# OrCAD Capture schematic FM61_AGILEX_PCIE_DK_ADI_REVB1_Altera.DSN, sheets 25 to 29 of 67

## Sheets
25 PCIe EP Edge Connector: size B
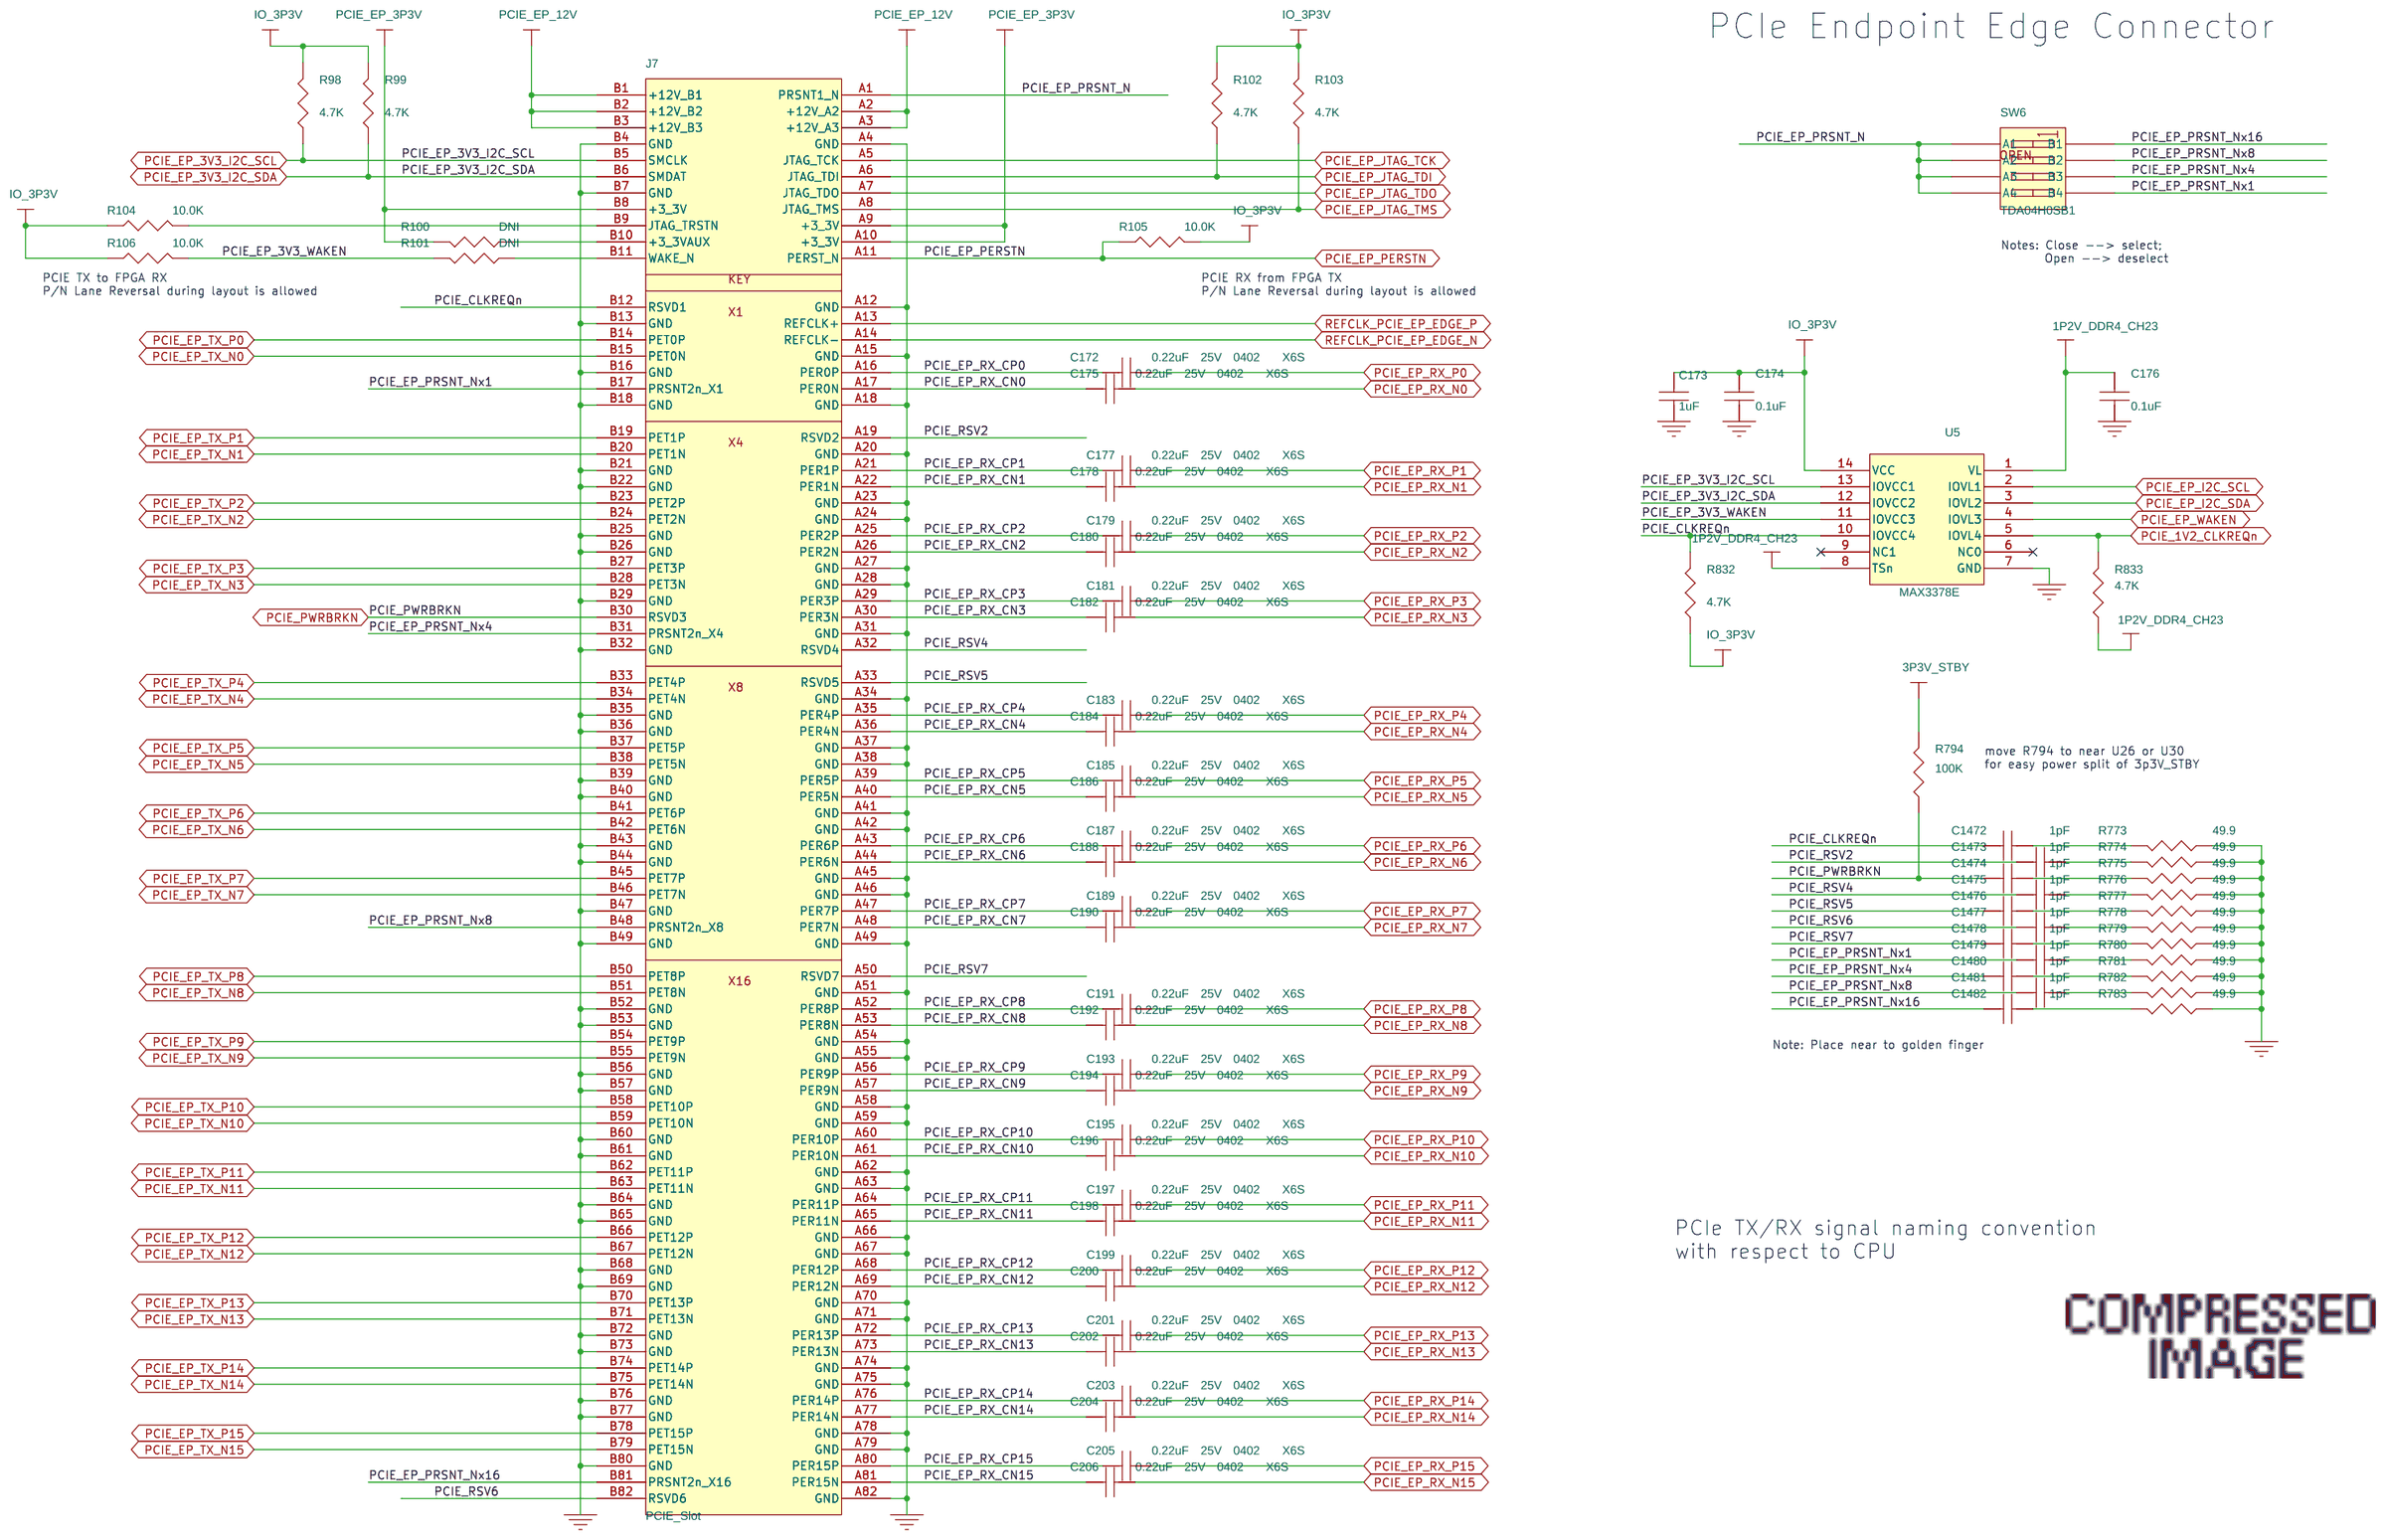
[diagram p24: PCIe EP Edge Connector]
26 FPGA BANK CONFIG SDM: size B
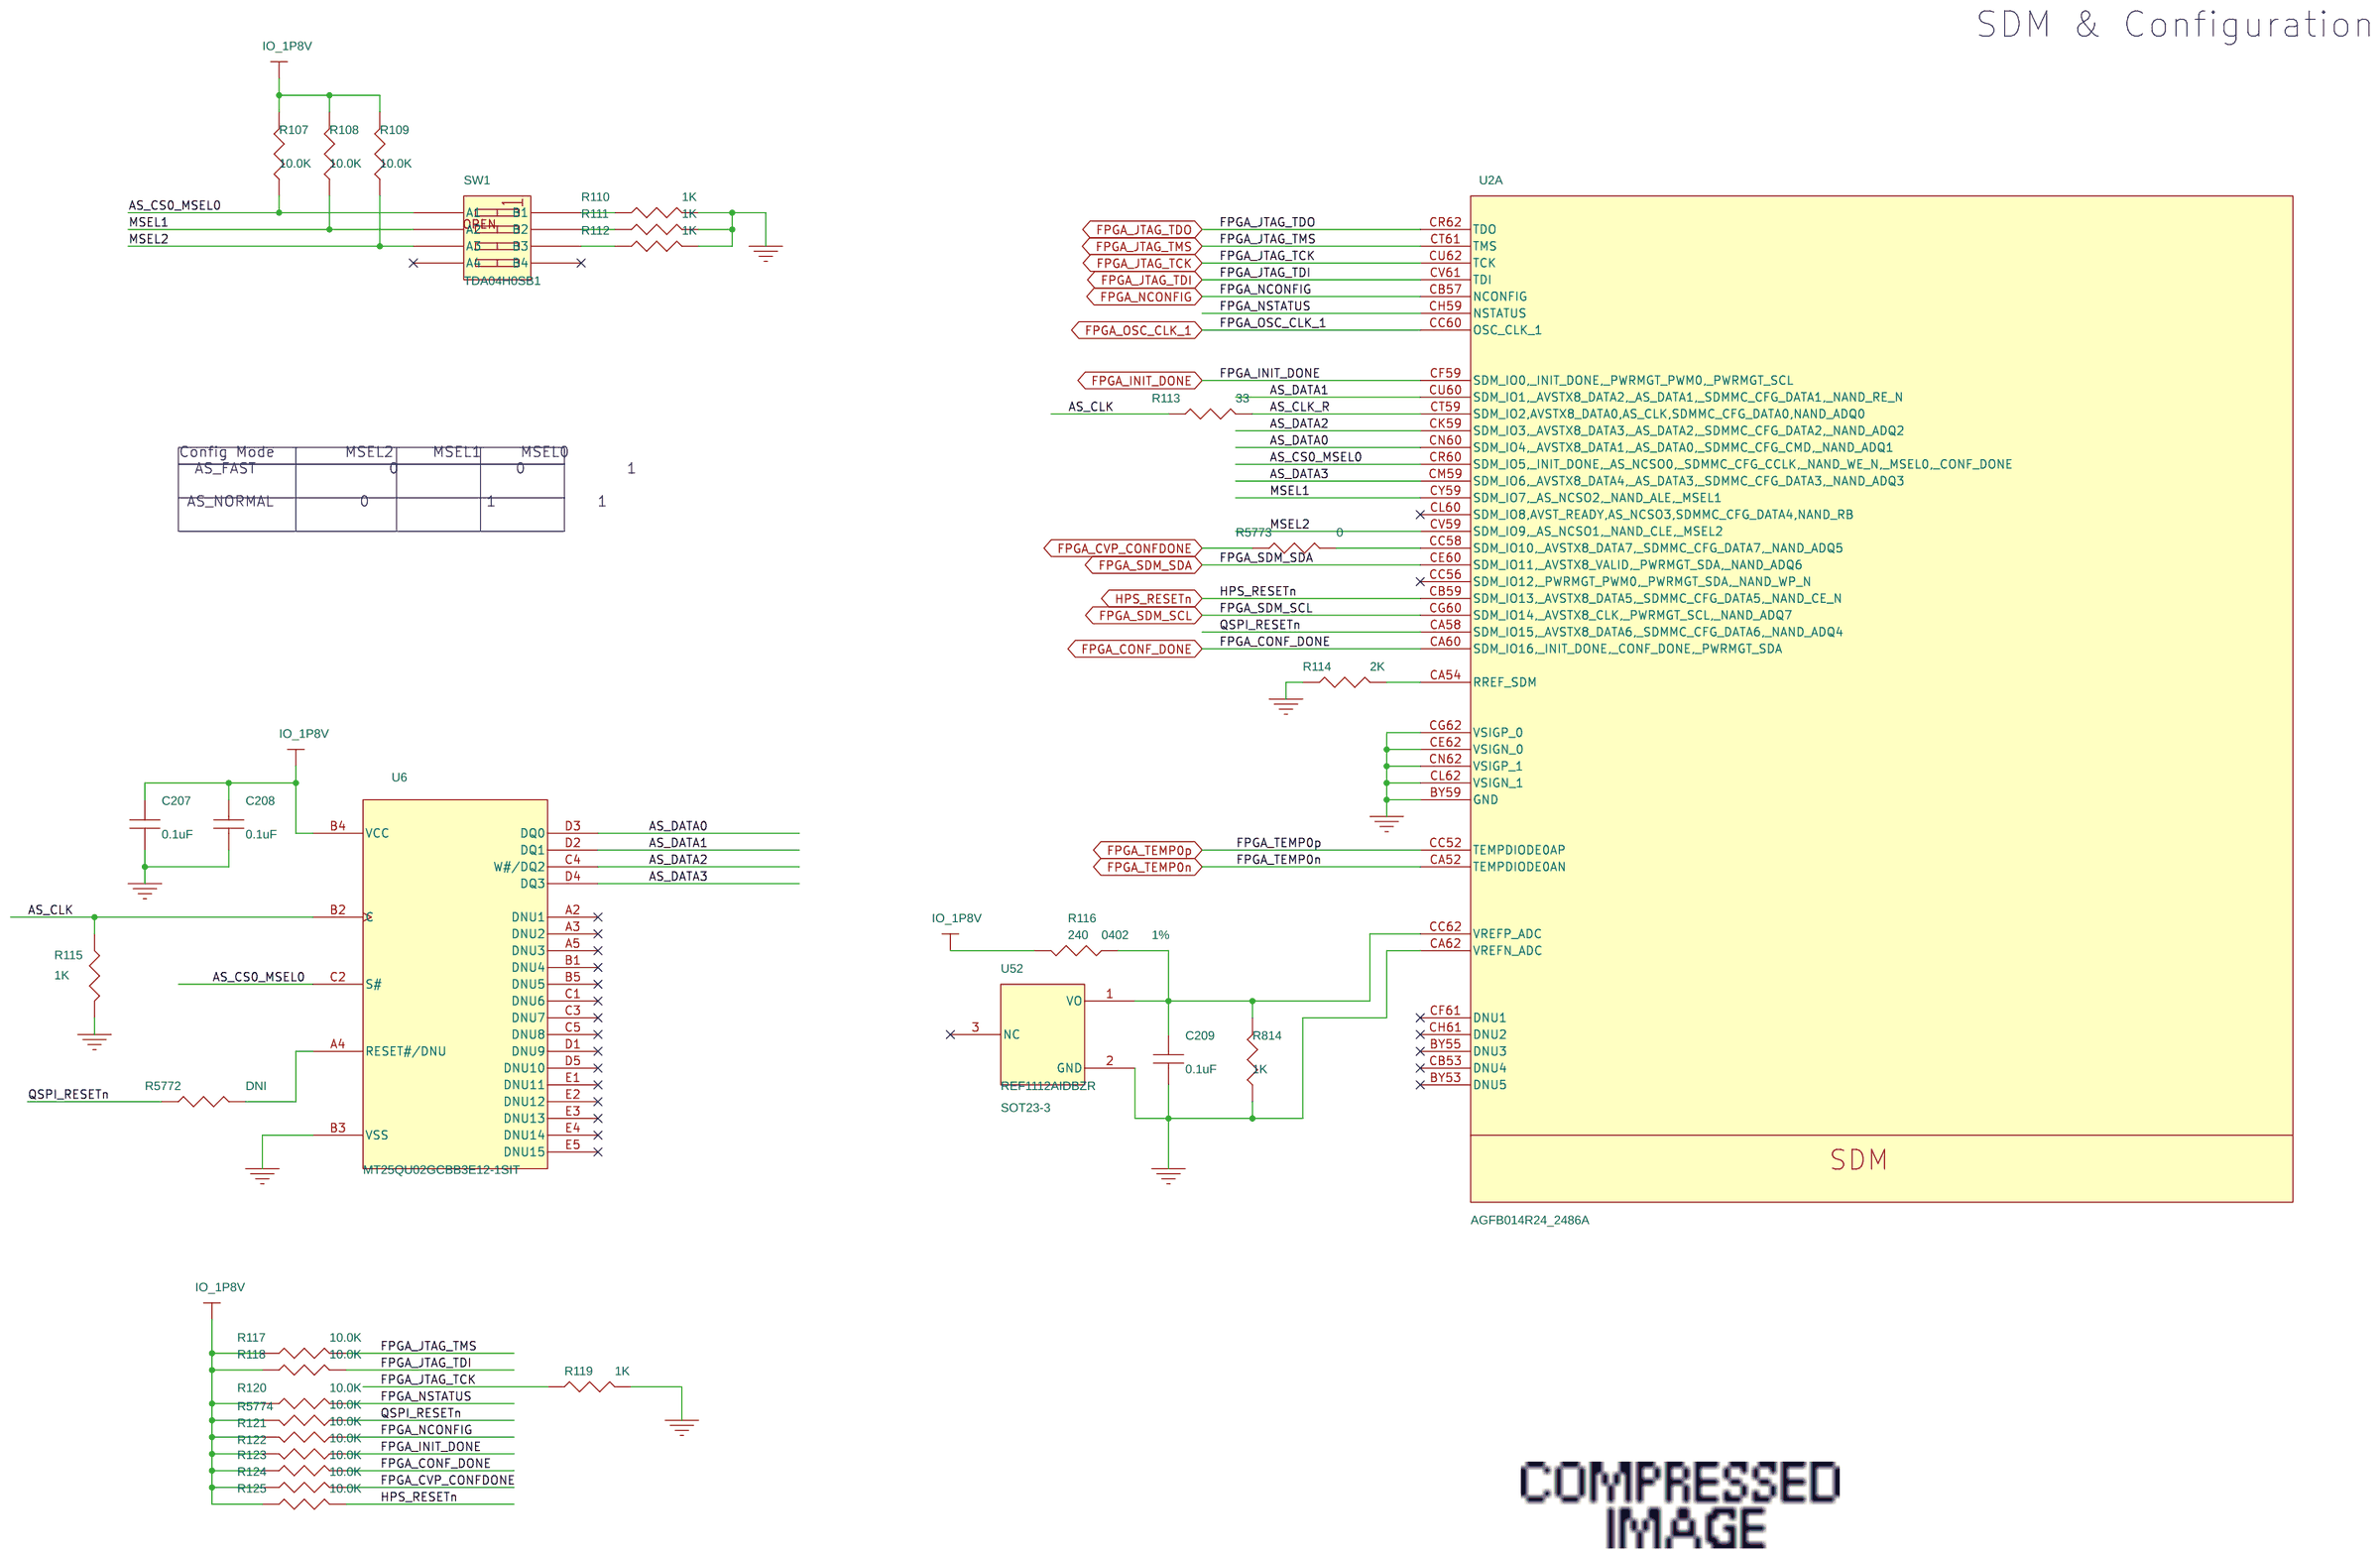
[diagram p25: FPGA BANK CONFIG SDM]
27 FPGA BANK HPS: size B
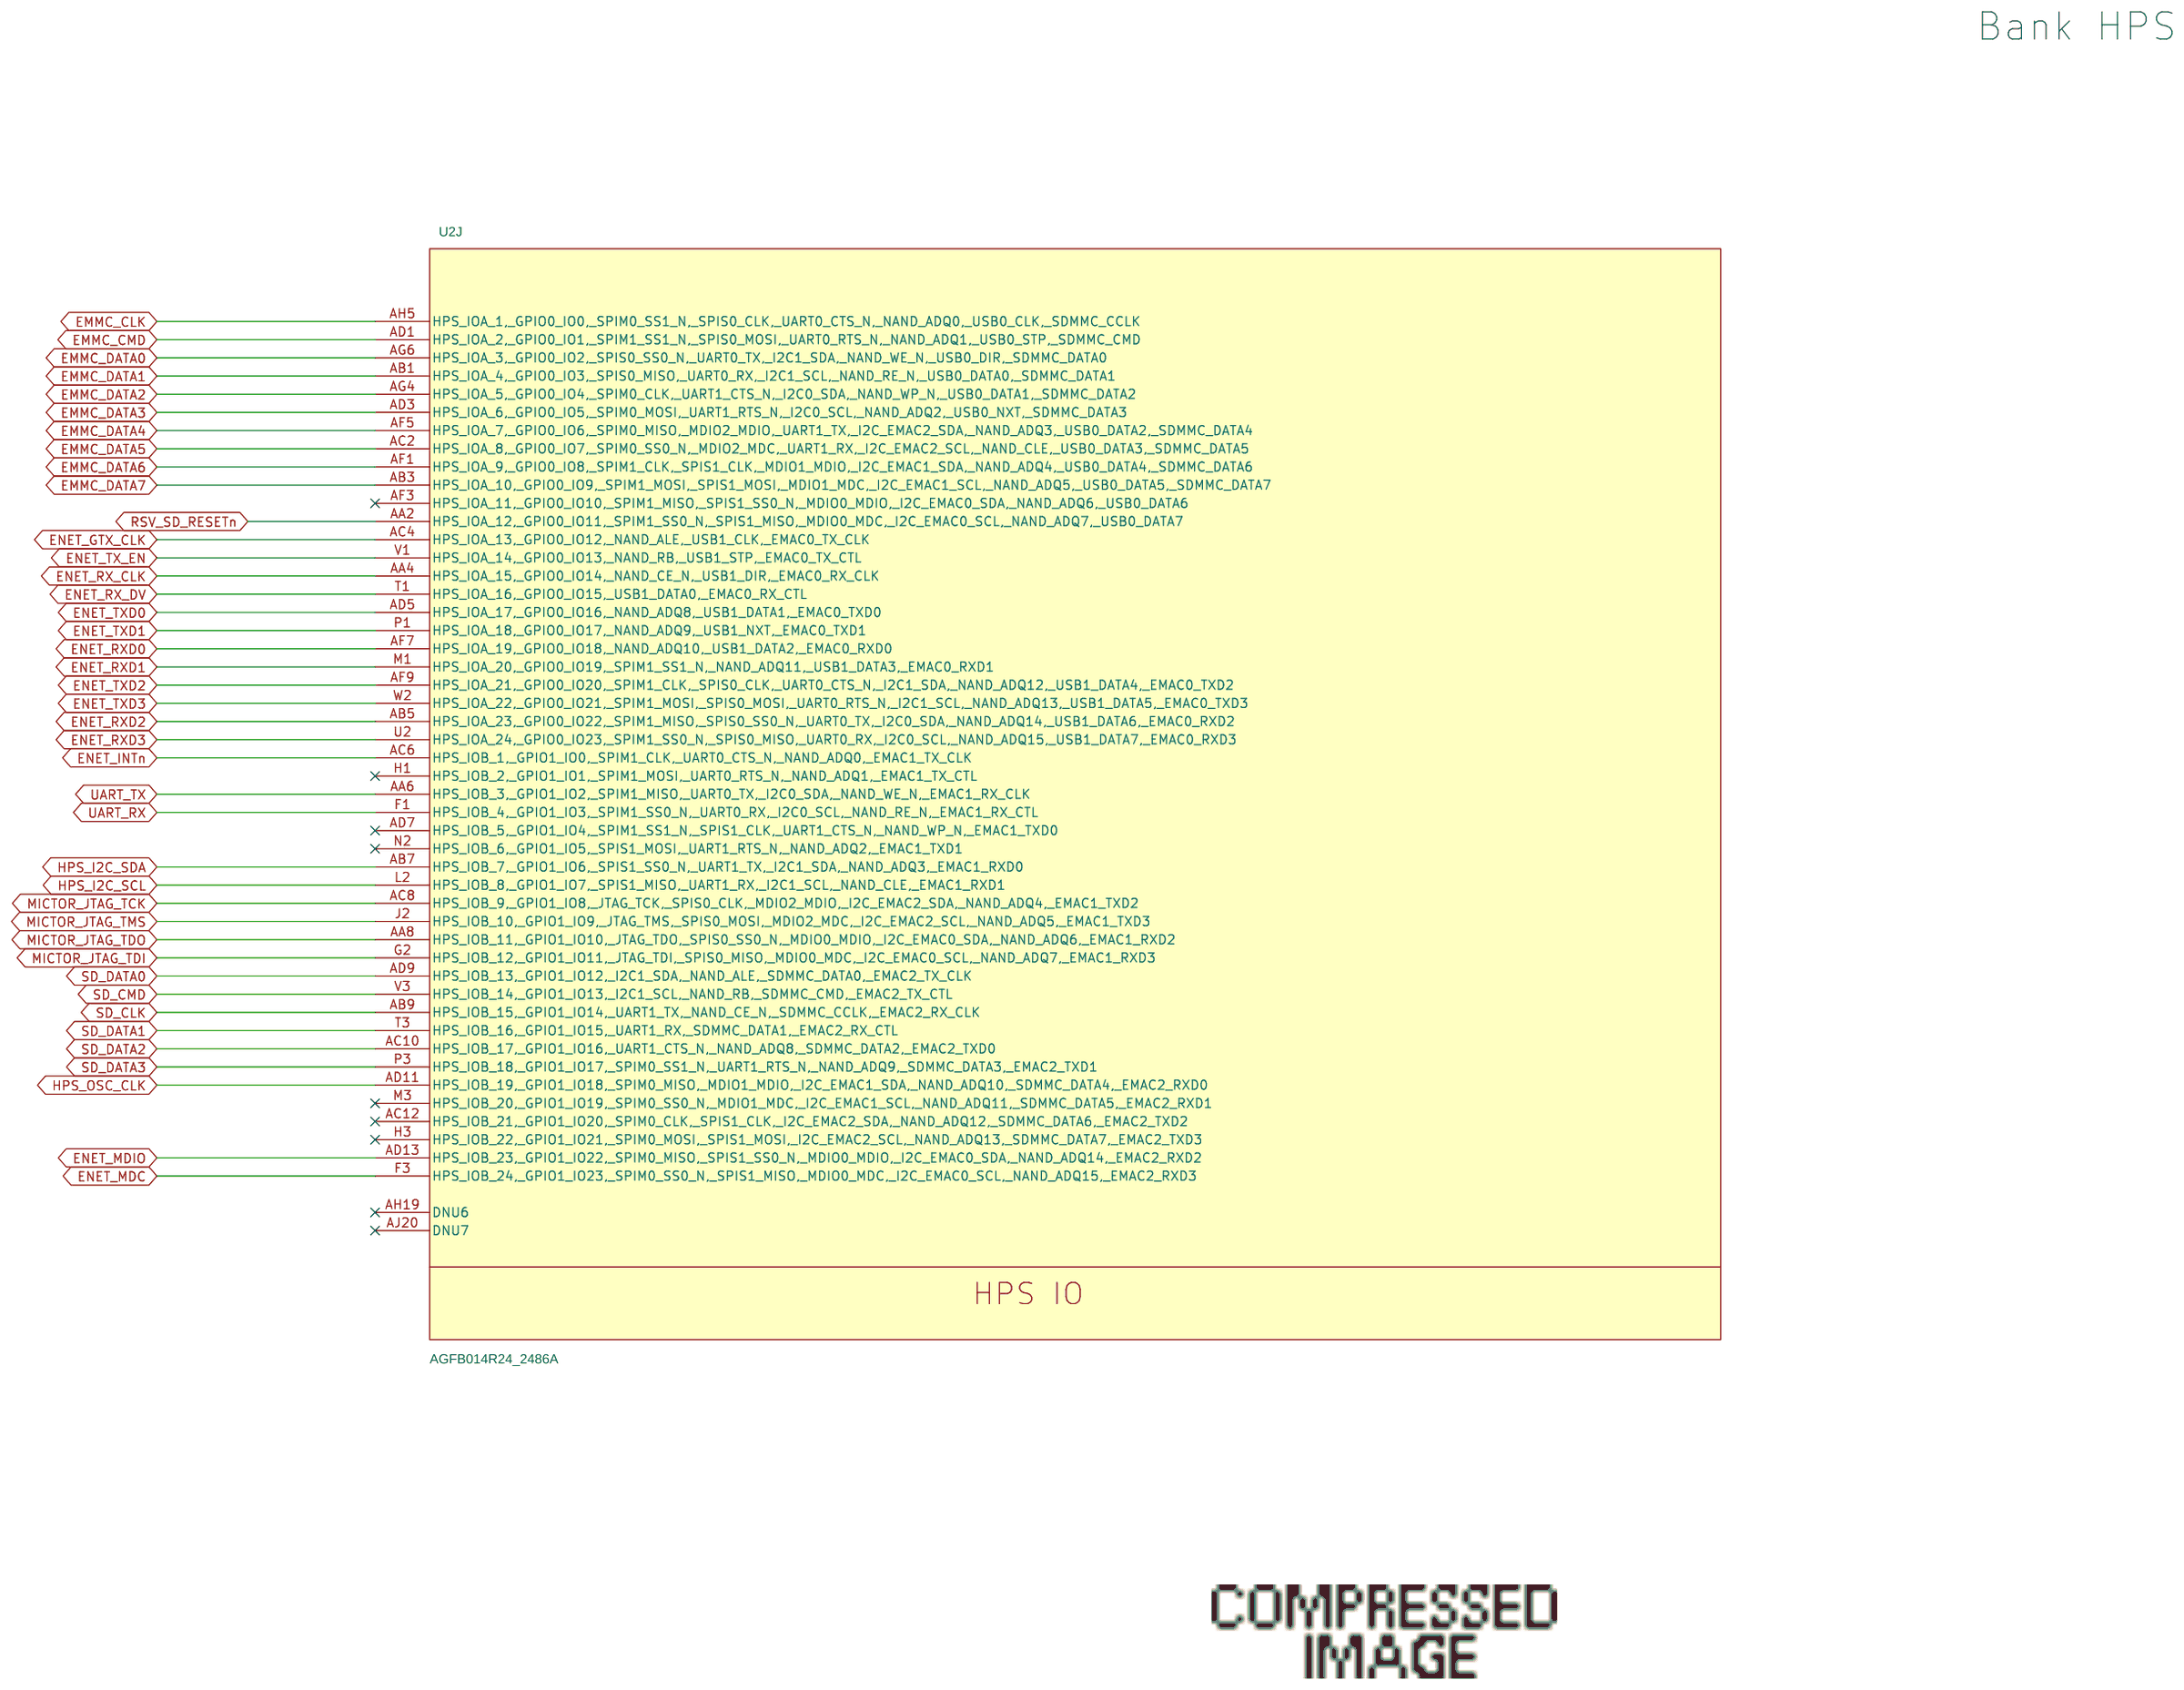
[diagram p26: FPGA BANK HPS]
28 Eth PHY: size B
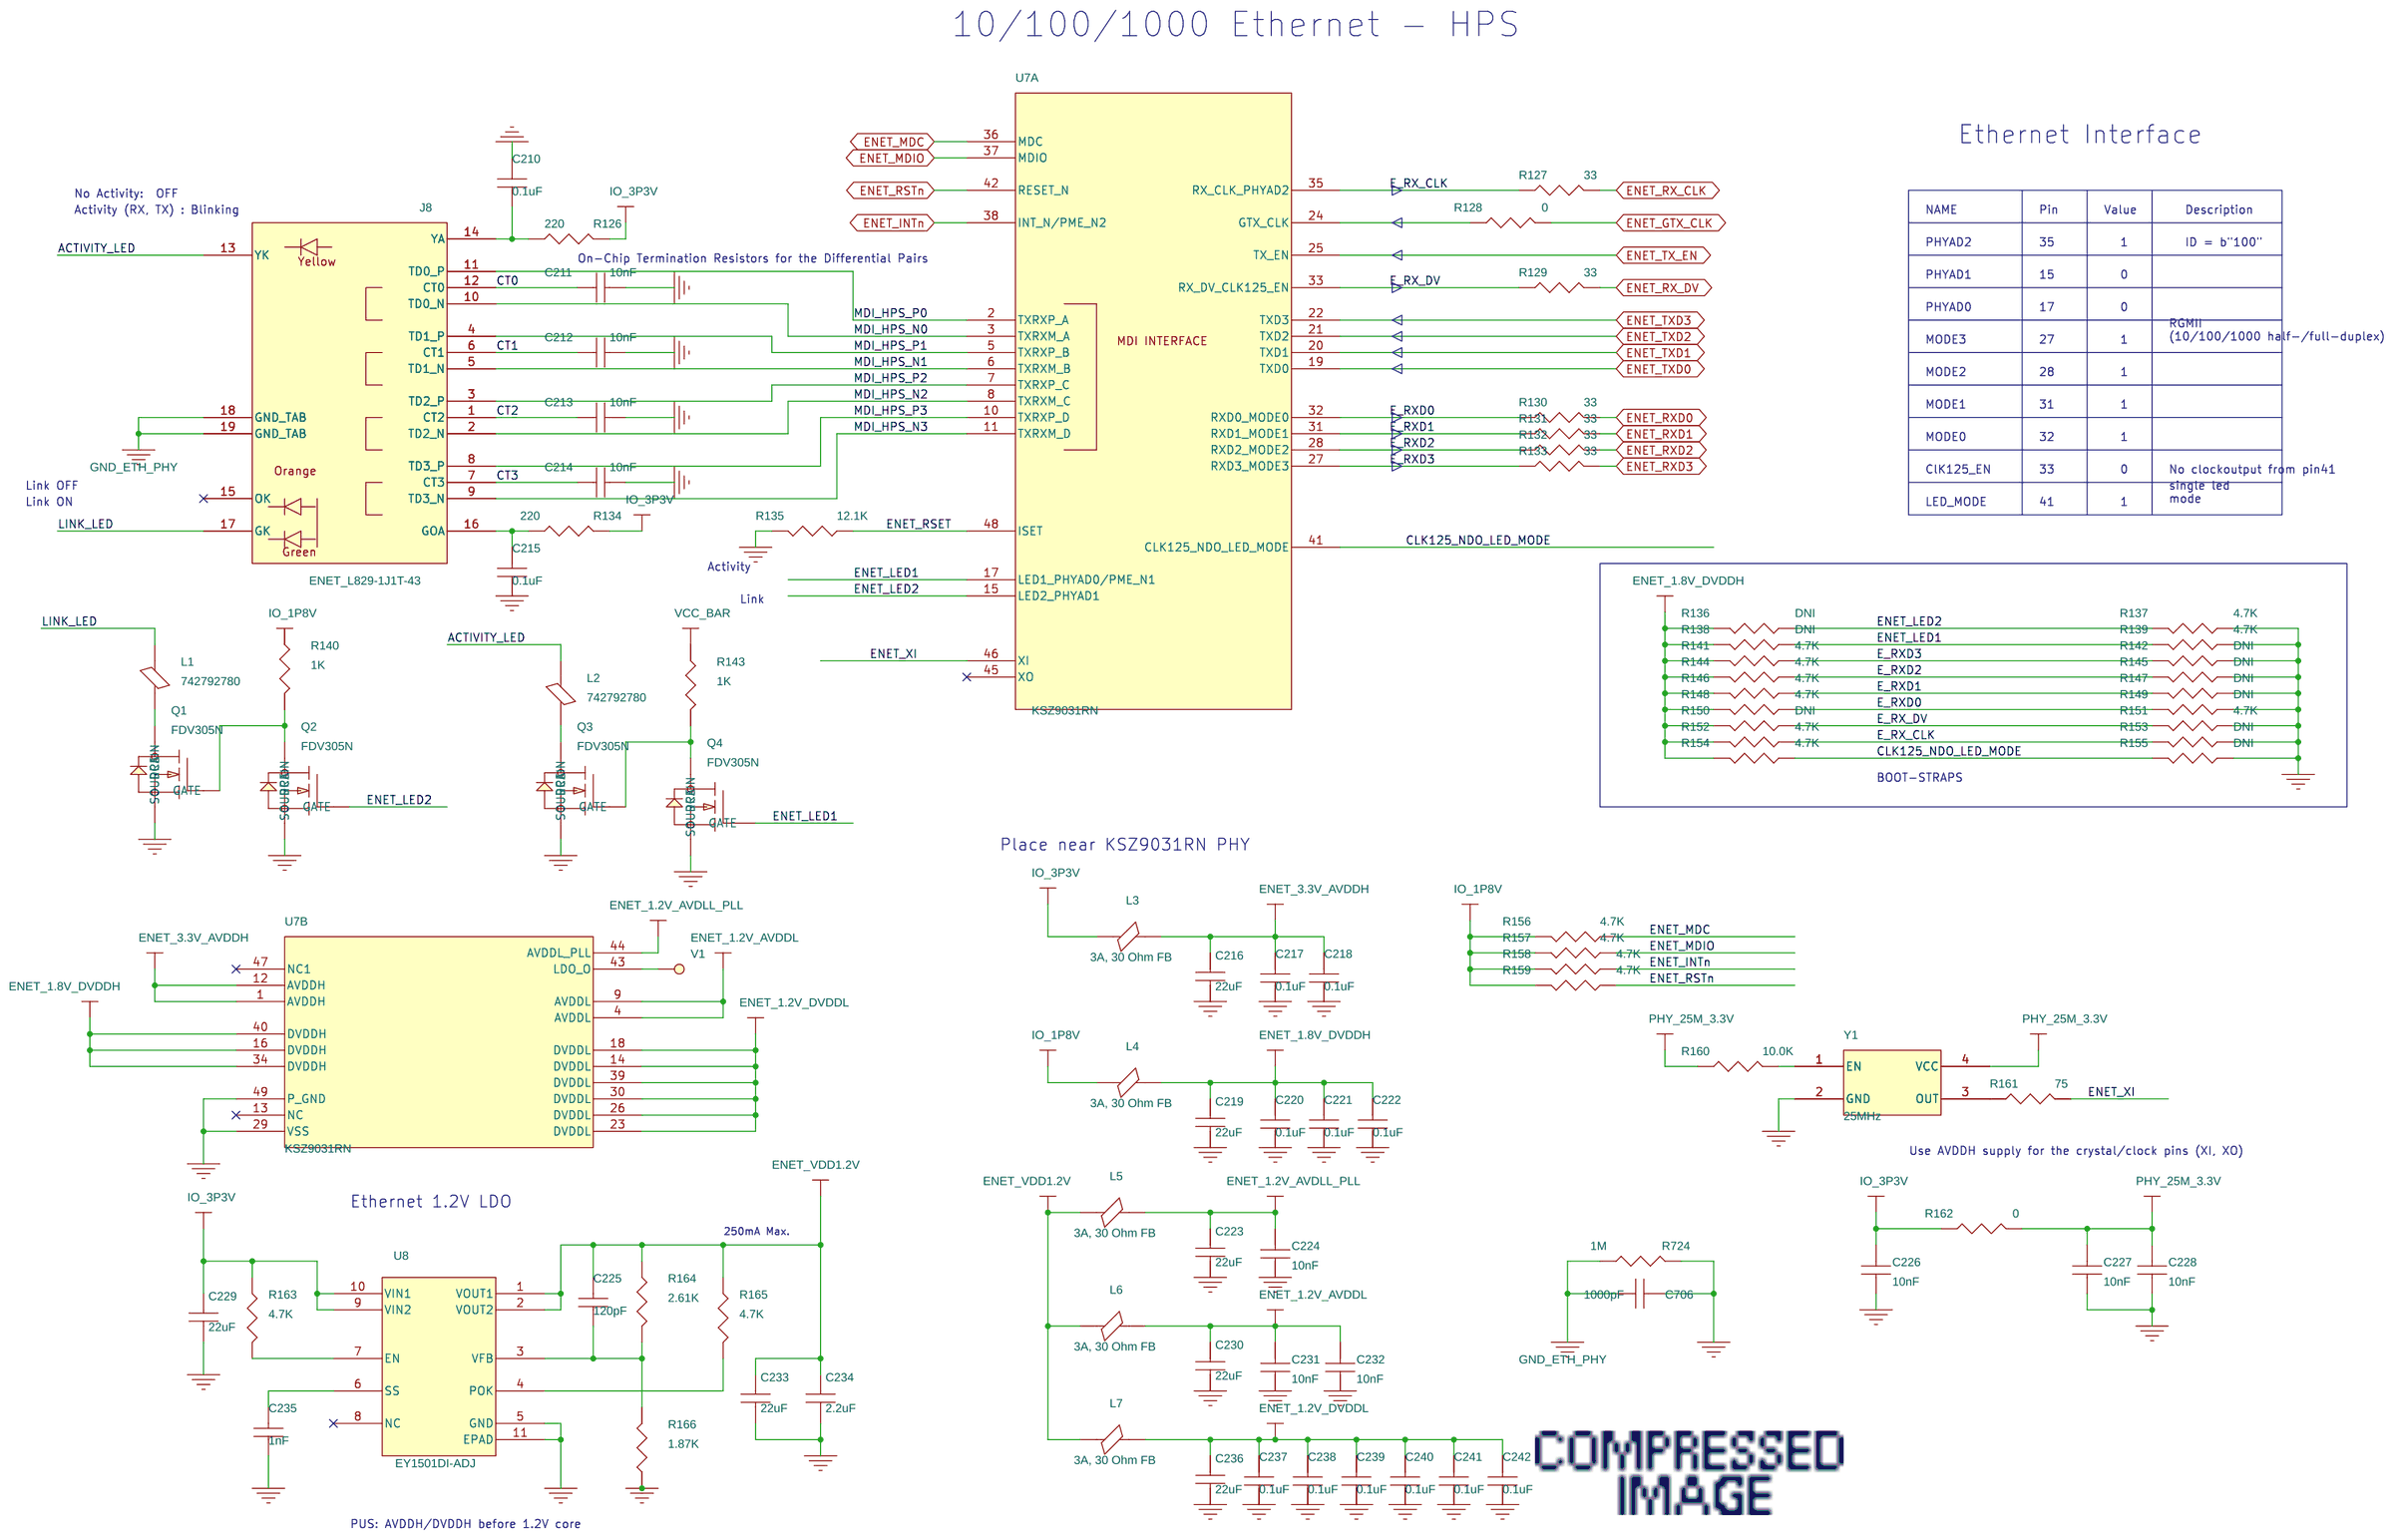
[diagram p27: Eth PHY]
29 UART: size B
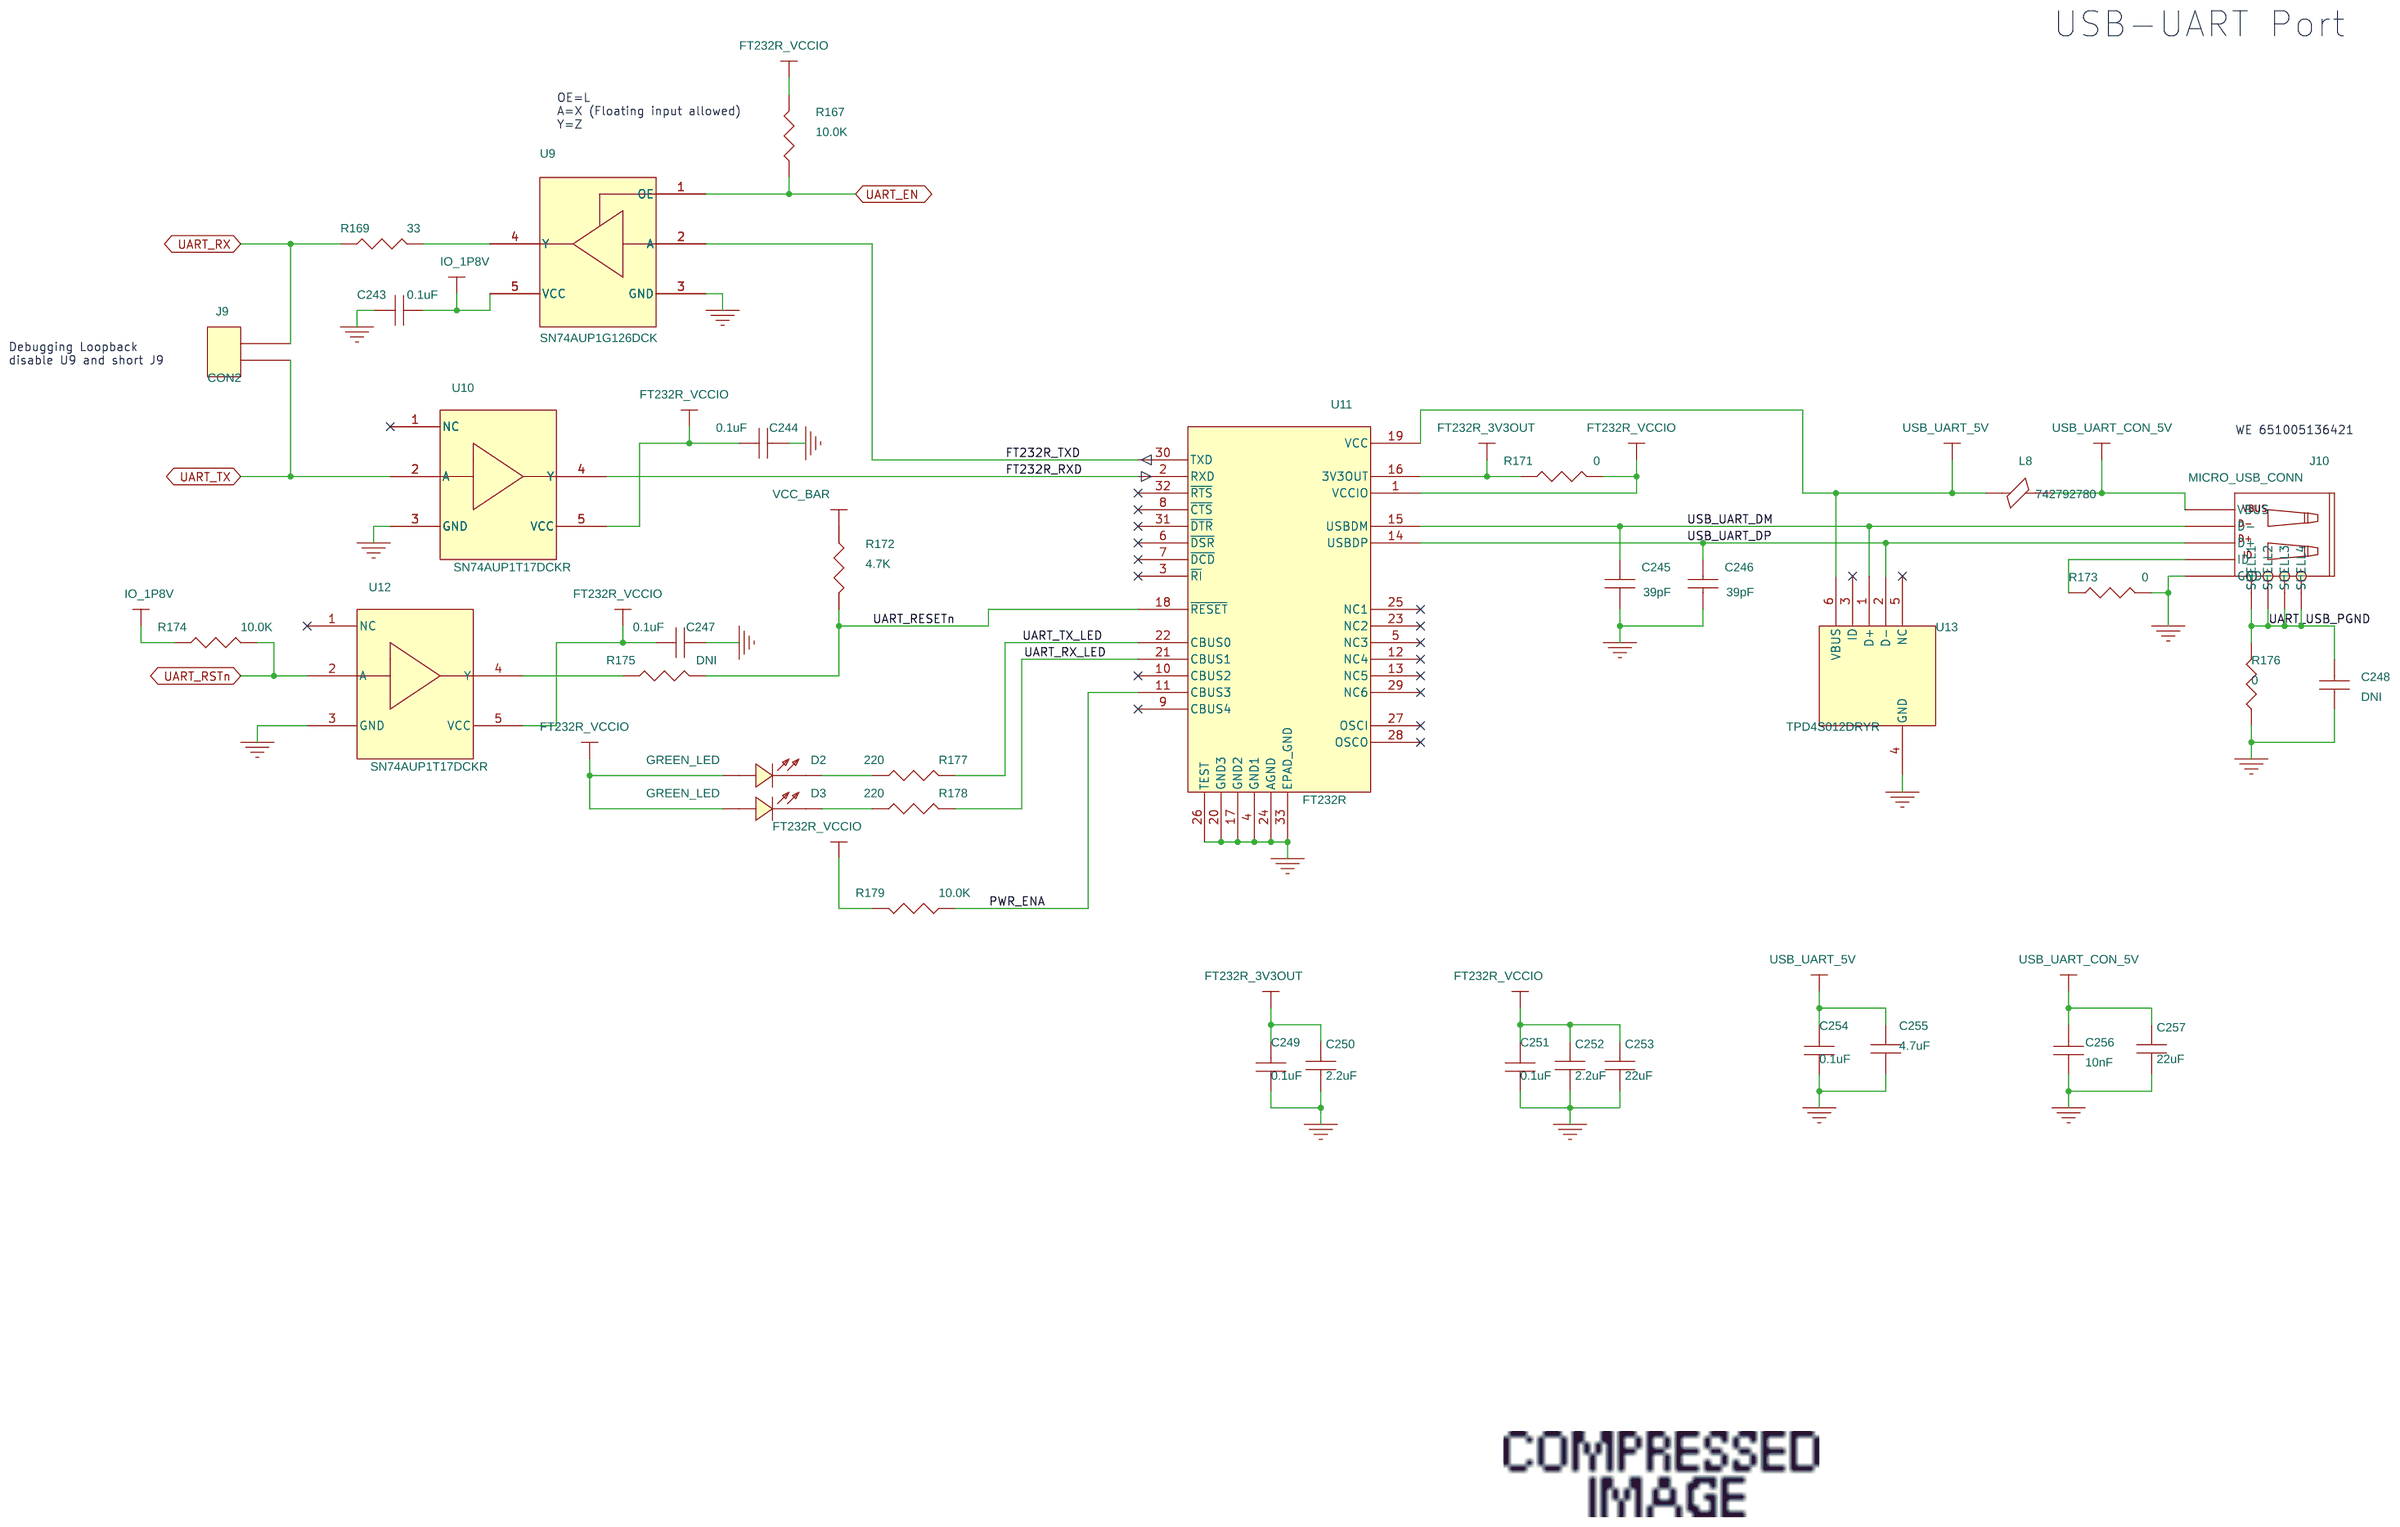
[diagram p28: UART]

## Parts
sheet Eth PHY
C210  0.1uF  [0402]
C211  10nF  [0402]
C212  10nF  [0402]
C213  10nF  [0402]
C214  10nF  [0402]
C215  0.1uF  [0402]
C216  22uF  [0603]
C217  0.1uF  [0402]
C218  0.1uF  [0402]
C219  22uF  [0603]
C220  0.1uF  [0402]
C221  0.1uF  [0402]
C222  0.1uF  [0402]
C223  22uF  [0603]
C224  10nF  [0402]
C225  120pF  [0402]
C226  10nF  [0402]
C227  10nF  [0402]
C228  10nF  [0402]
C229  22uF  [0603]
C230  22uF  [0603]
C231  10nF  [0402]
C232  10nF  [0402]
C233  22uF  [0603]
C234  2.2uF  [0603]
C235  1nF  [0402]
C236  22uF  [0603]
C237  0.1uF  [0402]
C238  0.1uF  [0402]
C239  0.1uF  [0402]
C240  0.1uF  [0402]
C241  0.1uF  [0402]
C242  0.1uF  [0402]
C706  1000pF  [1206]
J8  ENET_L829-1J1T-43  [bel_l829-1j1t-43]
L1  742792780  [0402]
L2  742792780  [0402]
L3  3A, 30 Ohm FB  [ind_0603]
L4  3A, 30 Ohm FB  [ind_0603]
L5  3A, 30 Ohm FB  [ind_0603]
L6  3A, 30 Ohm FB  [ind_0603]
L7  3A, 30 Ohm FB  [ind_0603]
Q1  FDV305N  [SOT23]
Q2  FDV305N  [SOT23]
Q3  FDV305N  [SOT23]
Q4  FDV305N  [SOT23]
R126  220  [0402]
R127  33  [0402]
R128  0  [0402]
R129  33  [0402]
R130  33  [0402]
R131  33  [0402]
R132  33  [0402]
R133  33  [0402]
R134  220  [0402]
R135  12.1K  [0402]
R136  DNI  [0402]
R137  4.7K  [0402]
R138  DNI  [0402]
R139  4.7K  [0402]
R140  1K  [0402]
R141  4.7K  [0402]
R142  DNI  [0402]
R143  1K  [0402]
R144  4.7K  [0402]
R145  DNI  [0402]
R146  4.7K  [0402]
R147  DNI  [0402]
R148  4.7K  [0402]
R149  DNI  [0402]
R150  DNI  [0402]
R151  4.7K  [0402]
R152  4.7K  [0402]
R153  DNI  [0402]
R154  4.7K  [0402]
R155  DNI  [0402]
R156  4.7K  [0402]
R157  4.7K  [0402]
R158  4.7K  [0402]
R159  4.7K  [0402]
R160  10.0K  [0402]
R161  75  [0402]
R162  0  [0402]
R163  4.7K  [0402]
R164  2.61K  [0402]
R165  4.7K  [0402]
R166  1.87K  [0402]
R724  1M  [0402]
U7  KSZ9031RN  [QFN48]  (sections A,B)
U8  EY1501DI-ADJ  [DFN-10]
V1  VIA_1  [STAR_VIA]
Y1  25MHz  [OSC7050]
sheet FPGA BANK CONFIG SDM
C207  0.1uF  [0402]
C208  0.1uF  [0402]
C209  0.1uF  [0402]
R107  10.0K  [0402]
R108  10.0K  [0402]
R109  10.0K  [0402]
R110  1K  [0402]
R111  1K  [0402]
R112  1K  [0402]
R113  33  [0402]
R114  2K  [0402]
R115  1K  [0402]
R116  240  [0402]
R117  10.0K  [0402]
R118  10.0K  [0402]
R119  1K  [0402]
R120  10.0K  [0402]
R121  10.0K  [0402]
R122  10.0K  [0402]
R123  10.0K  [0402]
R124  10.0K  [0402]
R125  10.0K  [0402]
R814  1K  [0402]
R5772  DNI  [0402]
R5773  0  [0402]
R5774  10.0K  [0402]
SW1  TDA04H0SB1  [DIPSWITCH_SMT_QUAD]
U6  MT25QU02GCBB3E12-1SIT  [T-PBGA24]
U52  REF1112AIDBZR  [SOT23-3]
sheet FPGA Gnd 2
U2  AGFB014R24_2486A  [FBGA2486A_HEX]  (sections A,B,C,D,E,F,G,H,I,J,K,L,M,N,O,P,Q,R,S,T,U,V,W,X)
sheet PCIe EP Edge Connector
C172  0.22uF  [0402]
C173  1uF  [0402]
C174  0.1uF  [0402]
C175  0.22uF  [0402]
C176  0.1uF  [0402]
C177  0.22uF  [0402]
C178  0.22uF  [0402]
C179  0.22uF  [0402]
C180  0.22uF  [0402]
C181  0.22uF  [0402]
C182  0.22uF  [0402]
C183  0.22uF  [0402]
C184  0.22uF  [0402]
C185  0.22uF  [0402]
C186  0.22uF  [0402]
C187  0.22uF  [0402]
C188  0.22uF  [0402]
C189  0.22uF  [0402]
C190  0.22uF  [0402]
C191  0.22uF  [0402]
C192  0.22uF  [0402]
C193  0.22uF  [0402]
C194  0.22uF  [0402]
C195  0.22uF  [0402]
C196  0.22uF  [0402]
C197  0.22uF  [0402]
C198  0.22uF  [0402]
C199  0.22uF  [0402]
C200  0.22uF  [0402]
C201  0.22uF  [0402]
C202  0.22uF  [0402]
C203  0.22uF  [0402]
C204  0.22uF  [0402]
C205  0.22uF  [0402]
C206  0.22uF  [0402]
C1472  1pF  [0402]
C1473  1pF  [0402]
C1474  1pF  [0402]
C1475  1pF  [0402]
C1476  1pF  [0402]
C1477  1pF  [0402]
C1478  1pF  [0402]
C1479  1pF  [0402]
C1480  1pF  [0402]
C1481  1pF  [0402]
C1482  1pF  [0402]
J7  PCIE_Slot  [PCIX-16PORT]
R98  4.7K  [0402]
R99  4.7K  [0402]
R100  DNI  [0402]
R101  DNI  [0402]
R102  4.7K  [0402]
R103  4.7K  [0402]
R104  10.0K  [0402]
R105  10.0K  [0402]
R106  10.0K  [0402]
R773  49.9  [0402]
R774  49.9  [0402]
R775  49.9  [0402]
R776  49.9  [0402]
R777  49.9  [0402]
R778  49.9  [0402]
R779  49.9  [0402]
R780  49.9  [0402]
R781  49.9  [0402]
R782  49.9  [0402]
R783  49.9  [0402]
R794  100K  [0402]
R832  4.7K  [0402]
R833  4.7K  [0402]
SW6  TDA04H0SB1  [DIPSWITCH_SMT_QUAD]
U5  MAX3378E  [TSSOP-14]
sheet UART
C243  0.1uF  [0402]
C244  0.1uF  [0402]
C245  39pF  [0402]
C246  39pF  [0402]
C247  0.1uF  [0402]
C248  DNI  [0402]
C249  0.1uF  [0402]
C250  2.2uF  [0603]
C251  0.1uF  [0402]
C252  2.2uF  [0603]
C253  22uF  [0603]
C254  0.1uF  [0402]
C255  4.7uF  [0805]
C256  10nF  [0402]
C257  22uF  [0603]
D2  GREEN_LED  [LED_0603]
D3  GREEN_LED  [LED_0603]
J9  CON2  [HDR2x1_100MIL]
J10  MICRO_USB_CONN  [molex-micro-usb-47589-001]
L8  742792780  [0402]
R167  10.0K  [0402]
R169  33  [0402]
R171  0  [0402]
R172  4.7K  [0402]
R173  0  [0402]
R174  10.0K  [0402]
R175  DNI  [0402]
R176  0  [0402]
R177  220  [0402]
R178  220  [0402]
R179  10.0K  [0402]
U9  SN74AUP1G126DCK  [SC70_TI]
U10  SN74AUP1T17DCKR  [SC70_TI]
U11  FT232R  [Qfn32-ftdi]
U12  SN74AUP1T17DCKR  [SC70_TI]
U13  TPD4S012DRYR  [SON6]

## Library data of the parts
C210 C215 C217 C218 C220-C222 C237-C242 = CAP: CAP CER 0.1UF 25V 20% X7R 0402; IPN: K13660-001; Item Num: P03-17618R; LIFECYCLE_PHASE: Active; Manufacturer: TDK Electronics; Manufacturer Part Num: C1005X7R1E104M; Price: 0; RoHS Compliant: RoHS Compliant
C211-C214 C224 C226-C228 C231 C232 C256 = CAP: CAP - CER, 10NF, 50V, +/-10%, X7R, 0402 SMD; IPN: A36096-100; Item Num: P03-16318R; Manufacturer: Murata; Manufacturer Part Num: GRM155R71H103KA88D; Price: 0; RoHS Compliant: RoHS Compliant
C216 C219 C223 C229 C230 C233 C236 C253 C257 = CAP: CAP 22UF CER 20% 6.3VDC X5R 0603 SMT; IPN: H48508-001; Item Num: P03-17794R; Manufacturer: Murata; Manufacturer Part Num: GRM188R60J226MEA0; Part Number: P03-17794R; Tolerance: +/-20%; Voltage: 6.3V
C225 = CAP: CAP - CER, 120PF, 50V, 5%, C0G, 0402; IPN: K13771-001; Item Num: P03-15872R; LIFECYCLE_PHASE: Active; Manufacturer: Murata; Manufacturer Part Num: GRM1555C1H121JA01D; Price: 0; RoHS Compliant: RoHS Compliant
C234 = CAP: CAP, CERAMIC, 2.2UF, 10%, 10VDC, X5R, 0603; IPN: K13568-001; Item Num: P03-15213R; LIFECYCLE_PHASE: Active; Manufacturer: Murata; Manufacturer Part Num: GRM188R61A225KE34x; RoHS Compliant: RoHS Compliant
C235 = CAP: CAP - CER, 1NF, 10%, 50V, X7R, 0402; IPN: G40798-001; Item Num: P03-15174R; LIFECYCLE_PHASE: Active; Manufacturer: Murata; Manufacturer Part Num: GRM155R71H102KA01D; Price: 0; RoHS Compliant: RoHS Compliant
C706 = CAP: CAP CER 1000PF 1000V X7R 1206; AGILE_LINK: http://sj-agile9app/Agile/PLMServlet?action=OpenEmailObject&classid=10000&objid=215384813; IPN: K13749-001; Item Num: P03-17910R; LIFECYCLE_PHASE: Active; Lead Free Status: Lead Free; MFR_LIFECYCLE: Active; Manufacturer: Murata; Manufacturer Part Num: GRM31BR73A102KW01L; Num Pins: 2; PACKAGING: Tape & Reel (TR); PART_SUBCLASS: CAPACITORS; RATED_VOLTAGE: 1000V; RoHS Compliant: RoHS Compliant; Supplier Part Num: GRM31BR73A102KW01L; Tolerance: +/-10%
J8 = ENET_L829-1J1T-43_2: CONN - RJ45 SINGLE PORT, 1000BASE-T GIGABIT ETHERNET MAGJACK 1 X 1 WITHLEDS, LOW PROFILE; IPN: C98527-001; Item Num: P23-38514R; Manufacturer: Bel Stewart Connector; Manufacturer Part Num: L829-1J1T-43; RoHS Compliant: RoHS Compliant
L1 L2 L8 = BEAD_FERRITE_SM: IND - SMD EMI FILTERS/CHIP FERRITE BEAD, 220-OHM @ 100MHZ, 0.35-OHM DCR, 0402; IPN: G79186-002; Item Num: P04-17068R; Manufacturer: Wurth Elektronik; Num Pins: 2; RoHS Compliant: RoHS Compliant
L3-L7 = IND_Ferrite_0603_3A_30_Ohms: IPN: K14405-001
Q1-Q4 = NMOS_3Pin: IC, MOSFET, N-CHANNEL, 20V; DCR: 0.3; IPN: K21465-001; Item Num: P18-31002R; Manufacturer: Fairchild Semiconductor; Voltage: 20V
R126 R134 = RESISTOR: RES, 220 OHMS, 5%, 1/16W, 0402; IPN: K15619-001; Item Num: P02-14107R; Manufacturer: Panasonic; Manufacturer Part Num: ERJ-2GEJ221X; Price: 0; RoHS Compliant: RoHS Compliant
R127 R129-R133 R169 = RESISTOR: RES 33 OHM 1/16W 5% 0402 SMD; IPN: K15753-001; Item Num: P02-14029R; LIFECYCLE_PHASE: Active; Manufacturer: Panasonic; Manufacturer Part Num: ERJ-2GEJ330X; RoHS Compliant: RoHS Compliant
R128 R162 R171 R173 = RESISTOR: RES ZERO OHM 1/16W 5% 0402 SMD; IPN: H30887-001; Item Num: P02-14020R; Manufacturer: Panasonic; Manufacturer Part Num: ERJ-2GE0R00X; Num Pins: 2; RoHS Compliant: RoHS Compliant
R135 = RESISTOR: RES-SMD 1/16watt 12.1Kohms 1% 0402; IPN: A93548-018; Item Num: P02-17669R; Manufacturer: Vishay; Manufacturer Part Num: CRCW040212K1FKED; Price: 0
R136 R138 R141 R142 R144-R151 R153 R154 R156-R159 R163 R165 = RESISTOR: RES,4.70K OHMS,1.0%,1/16W,0402; IPN: D60468-001; Item Num: P02-11384R; LIFECYCLE_PHASE: Active; Manufacturer: Vishay; Manufacturer Part Num: CRCW04024K70FKED; RoHS Compliant: RoHS Compliant
R137 R139 R152 R155 = RESISTOR: RES,4.70K OHMS,1.0%,1/16W,0402; IPN: D60468-001; Item Num: P02-11384R; LIFECYCLE_PHASE: Active; Manufacturer: Vishay; Manufacturer Part Num: CRCW04024K70FKED
R140 R143 = RESISTOR: RES,1.00K OHMS,1.0%,1/16W,0402; IPN: G60609-021; Item Num: P02-11372R; Manufacturer: Panasonic; Manufacturer Part Num: ERJ-2RKF1001X; Num Pins: 2; RoHS Compliant: RoHS Compliant
R160 R174 = RESISTOR: RES,10.0K OHMS,1.0%,1/16W, 0402; IPN: A93548-034; Item Num: P02-11364R; Manufacturer: Panasonic; Manufacturer Part Num: ERJ-2RKF1002X; Price: 0; RoHS Compliant: RoHS Compliant
R161 = RESISTOR: RES, 75 OHM, 5%, 1/16W, 0402; IPN: K15616-001; Item Num: P02-14103R; LIFECYCLE_PHASE: Active; Manufacturer: Panasonic; Manufacturer Part Num: ERJ-2RKF75ROX; Manufacturer Part Number: PANASONIC; RoHS Compliant: RoHS Compliant
R164 = R: RES - 2.61K OHM, 1%,1/10W, 0402 SMD; IPN: G41697-001; Item Num: P02-16710R; Manufacturer: Panasonic; Manufacturer Part Num: ERJ-2RKF2611x; Price: 0; RoHS Compliant: RoHS Compliant
R166 = RESISTOR: RES - 1.87K OHMS, 1.0%, 1/16W, 0402; IPN: K16301-001; Item Num: P02-16414R; Manufacturer: Vishay; Manufacturer Part Num: CRCW04021K87FKxx; RoHS Compliant: RoHS Compliant
R724 = RESISTOR: RES,1M OHMS,5.0%,1/16W,0402; AGILE_LINK: http://sj-agile9app/Agile/PLMServlet?action=OpenEmailObject&classid=10000&objid=146548997; IPN: K15866-001; Item Num: P02-11390R; LIFECYCLE_PHASE: Active; Lead Free Status: No; MFR_LIFECYCLE: Active; Manufacturer: Panasonic; Manufacturer Part Num: ERJ-2GEJ105X; Num Pins: 2; PART_SUBCLASS: RESISTORS; POWER: 1/16W; RoHS Compliant: Yes; TOLERANCE: +/-5%
U7 = KSZ9031RN_4: IC- PHY 1-CH 10MBPS/100MBPS/1GBPS 48-PIN QFN; IPN: J49350-001; Item Num: P01-17926R; Manufacturer: Micrel Semiconductor; Manufacturer Part Num: KSZ9031RNXCA; RoHS Compliant: RoHS Compliant
U8 = EY1501DI-ADJ: IC,LIN,DFN,ISL80101-AD,VREF; IPN: H38446-001; Item Num: P01-18061R; Manufacturer: Altera Corporation; Manufacturer Part Num: ISL80101IRAJZ-T
V1 = VIA_1
Y1 = OSC_ALT: OSC - CRYSTAL OSC. LVCMOS/LVTTL 25.000 MHZ OUTPUT SMT +/-50PPM; IPN: K14629-001; Item Num: P13-26150R; Manufacturer: ECS, Inc.; Manufacturer Part Num: ECS-3953C-250-B
C207-C209 = CAP: CAP CER 0.1UF 25V 20% X7R 0402; Dielectric: X5R; IPN: K13660-001; Item Num: P03-17618R; LIFECYCLE_PHASE: Active; Lead Free Status: Lead Free; Manufacturer: TDK Electronics; Manufacturer Part Num: C1005X7R1E104M; Num Pins: 2; Part Class: CAPACITORS; Price: 0.07; RoHS Compliant: RoHS Compliant; Tolerance: +80%/-20%
R104-R109 R117 R118 R120-R125 R167 R5774 = RESISTOR: RES,10.0K OHMS,1.0%,1/16W, 0402; AGILE_LINK: http://sj-agile9app/Agile/PLMServlet?action=OpenEmailObject&classid=10000&objid=146548997; IPN: A93548-034; Item Num: P02-11364R; LIFECYCLE_PHASE: Active; Lead Free Status: No; MFR_LIFECYCLE: Active; Manufacturer: Panasonic; Manufacturer Part Num: ERJ-2RKF1002X; Num Pins: 2; PART_SUBCLASS: RESISTORS; POWER: 1/16W; RoHS Compliant: Yes; TOLERANCE: +/-1%
R110-R112 R115 R119 R814 = RESISTOR: RES,1.00K OHMS,1.0%,1/16W,0402; IPN: G60609-021; Item Num: P02-11372R; Lead Free Status: No; Manufacturer: Panasonic; Manufacturer Part Num: ERJ-2RKF1001X; Num Pins: 2; Part Class: Resistors
R113 = RESISTOR_0402: RES 33 OHM 1/16W 5% 0402 SMD; IPN: K15753-001; Item Num: P02-14029R; Lead Free Status: No; Manufacturer: Panasonic; Manufacturer Part Num: ERJ-2GEJ330X; Num Pins: 2; Part Class: Resistors; Price: 0; RoHS Compliant: Yes
R114 = RESISTOR: RES 2K OHM 1/16W 1% 0402 SMD; IPN: J43524-001; Item Num: P02-17656R; Lead Free Status: Yes; Manufacturer: Panasonic; Manufacturer Part Num: ERJ-2RKF2001X; Num Pins: 2; Part Class: RESISTORS; Price: 0; RoHS Compliant: Yes
R116 = RESISTOR: RES - 240 OHM, 1/16W, 1%, 0402 SMD; IPN: K15783-001; Item Num: P02-15995R; Lead Free Status: No; Manufacturer: Panasonic; Manufacturer Part Num: ERJ-2RKF2400X; Num Pins: 2; Part Class: Resistors; TOLERANCE: 1%
R5772 = RESISTOR: RES ZERO OHM 1/16W 5% 0402 SMD; IPN: H30887-001; Item Num: P02-14020R; Lead Free Status: No; Manufacturer: Panasonic; Manufacturer Part Num: ERJ-2GE0R00X; Num Pins: 2; Part Class: RESISTORS; Price: 0; RoHS Compliant: Yes; Tolerance: 5%
R5773 = RESISTOR: RES ZERO OHM 1/16W 5% 0402 SMD; IPN: H30887-001; Item Num: P02-14020R; Lead Free Status: No; Manufacturer: Panasonic; Manufacturer Part Num: ERJ-2GE0R00X; Num Pins: 2; Part Class: RESISTORS; RoHS Compliant: Yes; Tolerance: 5%
SW1 SW6 = SPST4: SWITCHES - 4 POS, 8 PIN, Ultra-mini SMT Half-pitch Slider DIP Switch; IPN: K15518-001; Item Num: P11-24098R; Lead Free Status: Yes; Manufacturer: C & K Components/ITT Industries; Num Pins: 8; Part Class: Switches; Price: 0; RoHS Compliant: Yes; Supplier: 8
U6 = MT25QU01GBBB: IC, 2Gb 1.8V Serial NOR Flash Memory; IPN: K14016-001; Item Num: P01-18221R; Manufacturer: Micron
U52 = REF1112: IC VREF SHUNT 1.25V SOT23-3; IPN: K21883-001; Item Num: P01-XXXXXR; Manufacturer: Texas Instruments
U2 = FM6_2486A_V1.5: IPN: 99AH52
C172 C175 C177-C206 = CAP: CAP CER 0.22UF 25V X6S 0402; CAPACITANCE: 0.1uF; Dielectric: X6S; IPN: K19428-001; Item Num: P03-17969R; LIFECYCLE_PHASE: Active; Lead Free Status: Lead Free; Manufacturer: Murata; Manufacturer Part Num: GRT155C81E224KE01D; Num Pins: 2; Part Class: CAPACITORS; RATED_VOLTAGE: 25V; RoHS Compliant: RoHS Compliant; Tolerance: 10%
C173 = CAP: CAP, X5R, 1UF, 20%, 10V, 0402,; IPN: H67656-001; Item Num: P03-15479R; Lead Free Status: Yes; Manufacturer: Murata; Manufacturer Part Num: GRM155R61A105KE15D; Num Pins: 2; Part Class: CAPACITORS; RoHS Compliant: Yes; Voltage: 10V
C174 C176 = CAP: CAPC,Y5V,0402,0.1UF,25V,+80/-20%; Dielectric: Y5V; IPN: K13560-001; Item Num: P03-15057R; LIFECYCLE_PHASE: Active; Lead Free Status: Lead Free; MFR_LIFECYCLE: Active; Manufacturer: Murata; Manufacturer Part Num: GRM155F51E104ZA01D; Num Pins: 2; PART_SUBCLASS: CAPACITORS; Part Class: CAPACITORS; RATED_VOLTAGE: 25V; RoHS Compliant: RoHS Compliant; Tolerance: +80%/-20%
C1472-C1482 = CAP: CAP - CERAMIC, 1PF, +/-0.25PF,  50V, 0402, C0G; AGILE_LINK: http://sj-agile9app/Agile/PLMServlet?action=OpenEmailObject&classid=10000&objid=218192110; IPN: K13552-001; IPN No: K13552-001; Item Num: P03-15104R; LIFECYCLE_PHASE: Active; MFR_LIFECYCLE: Active; Manufacturer: Murata; Manufacturer Part Num: GJM1555C1H1R0CB01D; Num Pins: 2; PART_SUBCLASS: CAPACITORS; RATED_VOLTAGE: 50V; RoHS Compliant: RoHS Compliant
J7 = PCIE_Bracket_X16_1: Item Num: NA; Manufacturer: NA; Manufacturer's Part No.: NA
R98 R99 R102 R103 R832 R833 = RESISTOR: RES 4.7K OHM 1/16W 5% 0402 SMD; IPN: H30885-001; Item Num: P02-14032R; Lead Free Status: No; Manufacturer: Panasonic; Manufacturer Part Num: ERJ-2GEJ472X; Manufacturer's Part No.: ERJ-2GEJ472X; Num Pins: 2; Part Class: RESISTORS; Price: 0; RoHS Compliant: Yes
R100 R101 = RES_0_OHM_5%_1_16W_0402_SMD: IPN: H30887-001
R773-R783 = RESISTOR: RES, 49.9 OHMS, 1%, 1/16W, 0402; IPN: K16545-001; Item Num: P02-14101R; Lead Free Status: Yes; Manufacturer: NIC Components Corp.; Manufacturer Part Num: NRC04F49R9TRF; Num Pins: 2; Part Class: Resistors; Price: 0
R794 = RESISTOR: RES,100K OHMS,1.0%,1/16W,0402; IPN: E86804-001; Item Num: P02-11386R; Lead Free Status: No; Manufacturer: Panasonic; Manufacturer Part Num: ERJ-2RKF1003X; Num Pins: 2; POWER: 1/16W; Part Class: Resistors; Price: 0; RoHS Compliant: Yes; TOLERANCE: +/-1%
U5 = MAX3378E_0: IC - QUAD LOW-VOLTAGE LEVEL TRANSLATOR, +/- 15KV, ESD-PROTECTED, 1UA, 16MBPS; IPN: C34337-001; Item Num: P01-13191R; Manufacturer: Maxim; Manufacturer Part Num: MAX3378EEUD
C243 C244 C247 C249 C251 C254 = CAP: CAP CER 0.1UF 25V 20% X7R 0402; IPN: K13660-001; Item Num: P03-17618R; Manufacturer: TDK Electronics; Manufacturer Part Num: C1005X7R1E104M; RoHS Compliant: RoHS Compliant
C245 C246 = Cap_39PF_5%_50V_0402: IPN: K13765-001
C248 = CAP: CAP - CER 4700PF 50V 10% X7R 0402; AGILE_LINK: http://sj-agile9app/Agile/PLMServlet?action=OpenEmailObject&classid=10000&objid=215384813; CAPACITANCE: 4.7nF; IPN: A36096-066; Item Num: P03-15074R; LIFECYCLE_PHASE: Active; Lead Free Status: Lead Free; MFR_LIFECYCLE: Active; Manufacturer: Murata; Manufacturer Part Num: GRM155R71H472KA01D; Num Pins: 2; PACKAGING: Tape & Reel (TR); PART_SUBCLASS: CAPACITORS; RATED_VOLTAGE: 50V; RoHS Compliant: RoHS Compliant; Supplier Part Num: GRM155R71H472KA01D; Tolerance: +/-10%
C250 C252 = CAP: CAP, CERAMIC, 2.2UF, 10%, 10VDC, X5R, 0603; IPN: K13568-001; Item Num: P03-15213R; Manufacturer: Murata; Manufacturer Part Num: GRM188R61A225KE34x; RoHS Compliant: RoHS Compliant
C255 = CAP: CAP - CER, 4.7UF, 16V, X5R, 0805; IPN: K13548-001; Item Num: P03-15412R; Manufacturer: Murata; Manufacturer Part Num: GRM21BR61C475KA88L; Num Pins: 2; RoHS Compliant: RoHS Compliant
D2 D3 = LED_WURTH: LED - BRIGHT GREEN, VF=2V, IF=0.03A, 0603; IPN: K15375-001; Item Num: P09-21344R; LIFECYCLE_PHASE: Active; Manufacturer: Wurth Electroniks; Manufacturer Part Num: 150060VS75000; Num Pins: 2; RoHS Compliant: RoHS Compliant
J9 = CON2: 2x1.100''CENTER HEADER; IPN: J43365-001; Item Num: P23-38493R; Manufacturer: Wurth Elektroniks; Manufacturer Part Num: 613 002 111 21; Num Pins: 2; Price: 0; RoHS Compliant: RoHS Compliant
J10 = MICRO_USB_CONN: RECEPTACLE, USB 3.0, MICRO B, R/A; IPN: G68794-001; Item Num: P23-38552R; Lead Free Status: Yes; MFR_LIFECYCLE: Active; Manufacturer: Molex; Manufacturer Part Num: 47589-0001; Num Pins: 9; Part Class: Connectors; RoHS Compliant: Yes
R172 = RESISTOR: RES,4.70K OHMS,1.0%,1/16W,0402; IPN: D60468-001; Item Num: P02-11384R; Manufacturer: Vishay; Manufacturer Part Num: CRCW04024K70FKED; Num Pins: 2; Part Class: Resistors; RoHS Compliant: RoHS Compliant
R175 = RESISTOR: RES ZERO OHM 1/16W 5% 0402 SMD; IPN: H30887-001; Item Num: P02-14020R; Manufacturer: Panasonic; Manufacturer Part Num: ERJ-2GE0R00X; Num Pins: 2; Price: 0; RoHS Compliant: RoHS Compliant
R176 = RESISTOR: RES ZERO OHM 1/16W 5% 0402 SMD; Altera Part No.: P02-14020R; IPN: H30887-001; Item Num: P02-14020R; Lead Free Status: No; Manufacturer: Panasonic; Manufacturer Part Num: ERJ-2GE0R00X; Num Pins: 2; Part Class: RESISTORS; RoHS Compliant: Yes; Tolerance: 5%
R177 = RESISTOR: RES, 220 OHMS, 5%, 1/16W, 0402; IPN: K15619-001; Item Num: P02-14107R; Manufacturer: Panasonic; Manufacturer Part Num: ERJ-2GEJ221X; Num Pins: 2; Price: 0; RoHS Compliant: RoHS Compliant
R178 = RESISTOR: RES, 220 OHMS, 5%, 1/16W, 0402; IPN: K15619-001; Item Num: P02-14107R; Manufacturer: Panasonic; Manufacturer Part Num: ERJ-2GEJ221X; Num Pins: 2; Part Class: Resistors; Price: 0; RoHS Compliant: RoHS Compliant
R179 = RESISTOR: RES,10.0K OHMS,1.0%,1/16W, 0402; IPN: A93548-034; Item Num: P02-11364R; Manufacturer: Panasonic; Manufacturer Part Num: ERJ-2RKF1002X; Num Pins: 2; Price: 0; RoHS Compliant: RoHS Compliant
U9 = SN74AUP1G126DCK: IC - LOW-POWER SINGLE BUS BUFFER GATE WITH 3-STATE OUTPUT 3.6-V I/O TOLERANT; IPN: K14022-001; Item Num: P01-18133R; Manufacturer: Texas Instruments; Manufacturer Part Num: SN74AUP1G126DCKT
U10 U12 = SN74AUP1G17DCK: IC - SINGLE SCHMITT-TRIGGER BUFFER, 1.8/2.5/3.3V in, 3.3V CMOS out; IPN: K14023-001; Item Num: P01-18132R; Manufacturer: Texas Instruments
U11 = FT232R_2: IC - FTDI USB TO SERIAL UART INTERFACE, 32QFN; IPN: H40970-001; Item Num: P01-17819R; Manufacturer: FTDI; Manufacturer Part Num: FT232RQ-REEL; Num Pins: 32; RoHS Compliant: RoHS Compliant
U13 = TPD4S012DRYR: DIODE - HIGH SPEED, OTG, CHARGER USB ESD SOLUTION, 4CH, DRY; IPN: H38126-001; Item Num: P08-20820R; Manufacturer: Texas Instruments; Num Pins: 6; RoHS Compliant: RoHS Compliant

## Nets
GND: C173.2 C174.2 C176.2 C207.2 C208.2 C209.2 C210.2 C211.2 C212.2 C213.2 C214.2 C215.1 C216.2 C217.1 C218.1 C219.2 C220.1 C221.1 C222.1 C223.2 C224.1 C226.1 C227.1 C228.1 C229.2 C230.2 C231.1 C232.1 C233.2 C234.2 C235.1 C236.2 C237.1 C238.1 C239.1 C240.1 C241.1 C242.1 C243.2 C244.2 C245.2 C246.2 C247.2 C248.1 C249.1 C250.2 C251.1 C252.2 C253.2 C254.1 C255.2 C256.1 C257.2 C706.2 J7.A4(GND) J7.A12(GND) J7.A15(GND) J7.A18(GND) J7.A20(GND) J7.A23(GND) J7.A24(GND) J7.A27(GND) J7.A28(GND) J7.A31(GND) J7.A34(GND) J7.A37(GND) J7.A38(GND) J7.A41(GND) J7.A42(GND) J7.A45(GND) J7.A46(GND) J7.A49(GND) J7.A51(GND) J7.A54(GND) J7.A55(GND) J7.A58(GND) J7.A59(GND) J7.A62(GND) J7.A63(GND) J7.A66(GND) J7.A67(GND) J7.A70(GND) J7.A71(GND) J7.A74(GND) J7.A75(GND) J7.A78(GND) J7.A79(GND) J7.A82(GND) J7.B4(GND) J7.B7(GND) J7.B13(GND) J7.B16(GND) J7.B18(GND) J7.B21(GND) J7.B22(GND) J7.B25(GND) J7.B26(GND) J7.B29(GND) J7.B32(GND) J7.B35(GND) J7.B36(GND) J7.B39(GND) J7.B40(GND) J7.B43(GND) J7.B44(GND) J7.B47(GND) J7.B49(GND) J7.B52(GND) J7.B53(GND) J7.B56(GND) J7.B57(GND) J7.B60(GND) J7.B61(GND) J7.B64(GND) J7.B65(GND) J7.B68(GND) J7.B69(GND) J7.B72(GND) J7.B73(GND) J7.B76(GND) J7.B77(GND) J7.B80(GND) J10.5(GND) Q1.2(SOURCE) Q2.2(SOURCE) Q3.2(SOURCE) Q4.2(SOURCE) R110.1 R111.1 R112.1 R114.1 R115.1 R119.1 R135.2 R137.2 R139.2 R142.2 R145.2 R147.2 R149.2 R151.2 R153.2 R155.2 R166.1 R173.2 R176.1 R724.1 R773.1 R774.1 R775.1 R776.1 R777.1 R778.1 R779.1 R780.1 R781.1 R782.1 R783.1 R814.2 U2.BY59(GND) U2.CA62(VREFN_ADC) U2.CE62(VSIGN_0) U2.CG62(VSIGP_0) U2.CL62(VSIGN_1) U2.CN62(VSIGP_1) U5.7(GND) U6.B3(VSS) U7.29(VSS) U7.49(P_GND) U8.5(GND) U8.11(EPAD) U9.3(GND) U10.3(GND) U11.4(GND1) U11.17(GND2) U11.20(GND3) U11.24(AGND) U11.26(TEST) U11.33(EPAD_GND) U12.3(GND) U13.4(GND) U52.2(GND) Y1.2(GND) ; also on sheet 9 11 12 13 14 15 17 18 20 21 22 23 24 30 31 32 34 35 36 37 38 39 40 41 42 43 44 45 46 47 48 49 50 51 52 53 54 55 56 57 58 59 60 61 62 63 64 65 66
GND_ETH_PHY: C706.1 J8.18(GND_TAB) J8.19(GND_TAB) R724.2
1p2V_DDR4_CH23: C176.1 R833.1 U5.1(VL) U5.8(TSn) ; also on sheet 15 16 18 19 34 46 61 62 66
3p3V_STBY: R794.1 ; also on sheet 39 41 43 44 46 47 48 49 62
ACTIVITY_LED: J8.13(YK) L2.2
AS_CLK: R113.1 R115.2 U6.B2(C)
AS_CLK_R: R113.2 U2.CT59(SDM_IO2,AVSTX8_DATA0,AS_CLK,SDMMC_CFG_DATA0,NAND_ADQ0)
AS_CS0_MSEL0: R107.1 SW1.1(A1) U2.CR60(SDM_IO5,_INIT_DONE,_AS_NCSO0,_SDMMC_CFG_CCLK,_NAND_WE_N,_MSEL0,_CONF_DONE) U6.C2(S#)
AS_DATA0: U2.CN60(SDM_IO4,_AVSTX8_DATA1,_AS_DATA0,_SDMMC_CFG_CMD,_NAND_ADQ1) U6.D3(DQ0)
AS_DATA1: U2.CU60(SDM_IO1,_AVSTX8_DATA2,_AS_DATA1,_SDMMC_CFG_DATA1,_NAND_RE_N) U6.D2(DQ1)
AS_DATA2: U2.CK59(SDM_IO3,_AVSTX8_DATA3,_AS_DATA2,_SDMMC_CFG_DATA2,_NAND_ADQ2) U6.C4(W#/DQ2)
AS_DATA3: U2.CM59(SDM_IO6,_AVSTX8_DATA4,_AS_DATA3,_SDMMC_CFG_DATA3,_NAND_ADQ3) U6.D4(DQ3)
CLK125_NDO_LED_MODE: R154.2 R155.1 U7.41(CLK125_NDO_LED_MODE)
CT0: C211.1 J8.12(CT0)
CT1: C212.1 J8.6(CT1)
CT2: C213.1 J8.1(CT2)
CT3: C214.1 J8.7(CT3)
E_RX_CLK: R127.1 R152.2 R153.1 U7.35(RX_CLK_PHYAD2)
E_RX_DV: R129.1 R150.2 R151.1 U7.33(RX_DV_CLK125_EN)
E_RXD0: R130.1 R148.2 R149.1 U7.32(RXD0_MODE0)
E_RXD1: R131.1 R146.2 R147.1 U7.31(RXD1_MODE1)
E_RXD2: R132.1 R144.2 R145.1 U7.28(RXD2_MODE2)
E_RXD3: R133.1 R141.2 R142.1 U7.27(RXD3_MODE3)
EMMC_CLK: U2.AH5(HPS_IOA_1,_GPIO0_IO0,_SPIM0_SS1_N,_SPIS0_CLK,_UART0_CTS_N,_NAND_ADQ0,_USB0_CLK,_SDMMC_CCLK) ; also on sheet 31
EMMC_CMD: U2.AD1(HPS_IOA_2,_GPIO0_IO1,_SPIM1_SS1_N,_SPIS0_MOSI,_UART0_RTS_N,_NAND_ADQ1,_USB0_STP,_SDMMC_CMD) ; also on sheet 31
EMMC_DATA0: U2.AG6(HPS_IOA_3,_GPIO0_IO2,_SPIS0_SS0_N,_UART0_TX,_I2C1_SDA,_NAND_WE_N,_USB0_DIR,_SDMMC_DATA0) ; also on sheet 31
EMMC_DATA1: U2.AB1(HPS_IOA_4,_GPIO0_IO3,_SPIS0_MISO,_UART0_RX,_I2C1_SCL,_NAND_RE_N,_USB0_DATA0,_SDMMC_DATA1) ; also on sheet 31
EMMC_DATA2: U2.AG4(HPS_IOA_5,_GPIO0_IO4,_SPIM0_CLK,_UART1_CTS_N,_I2C0_SDA,_NAND_WP_N,_USB0_DATA1,_SDMMC_DATA2) ; also on sheet 31
EMMC_DATA3: U2.AD3(HPS_IOA_6,_GPIO0_IO5,_SPIM0_MOSI,_UART1_RTS_N,_I2C0_SCL,_NAND_ADQ2,_USB0_NXT,_SDMMC_DATA3) ; also on sheet 31
EMMC_DATA4: U2.AF5(HPS_IOA_7,_GPIO0_IO6,_SPIM0_MISO,_MDIO2_MDIO,_UART1_TX,_I2C_EMAC2_SDA,_NAND_ADQ3,_USB0_DATA2,_SDMMC_DATA4) ; also on sheet 31
EMMC_DATA5: U2.AC2(HPS_IOA_8,_GPIO0_IO7,_SPIM0_SS0_N,_MDIO2_MDC,_UART1_RX,_I2C_EMAC2_SCL,_NAND_CLE,_USB0_DATA3,_SDMMC_DATA5) ; also on sheet 31
EMMC_DATA6: U2.AF1(HPS_IOA_9,_GPIO0_IO8,_SPIM1_CLK,_SPIS1_CLK,_MDIO1_MDIO,_I2C_EMAC1_SDA,_NAND_ADQ4,_USB0_DATA4,_SDMMC_DATA6) ; also on sheet 31
EMMC_DATA7: U2.AB3(HPS_IOA_10,_GPIO0_IO9,_SPIM1_MOSI,_SPIS1_MOSI,_MDIO1_MDC,_I2C_EMAC1_SCL,_NAND_ADQ5,_USB0_DATA5,_SDMMC_DATA7) ; also on sheet 31
ENET_1.2V_AVDDL: C230.1 C231.2 C232.2 L6.2 U7.4(AVDDL) U7.9(AVDDL)
ENET_1.2V_AVDLL_PLL: C223.1 C224.2 L5.2 U7.44(AVDDL_PLL)
ENET_1.2V_DVDDL: C236.1 C237.2 C238.2 C239.2 C240.2 C241.2 C242.2 L7.2 U7.14(DVDDL) U7.18(DVDDL) U7.23(DVDDL) U7.26(DVDDL) U7.30(DVDDL) U7.39(DVDDL)
ENET_1.8V_DVDDH: C219.1 C220.2 C221.2 C222.2 L4.2 R136.1 R138.1 R141.1 R144.1 R146.1 R148.1 R150.1 R152.1 R154.1 U7.16(DVDDH) U7.34(DVDDH) U7.40(DVDDH)
ENET_3.3V_AVDDH: C216.1 C217.2 C218.2 L3.2 U7.1(AVDDH) U7.12(AVDDH)
ENET_GTX_CLK: R128.2 U2.AC4(HPS_IOA_13,_GPIO0_IO12,_NAND_ALE,_USB1_CLK,_EMAC0_TX_CLK)
ENET_INTn: R158.2 U2.AC6(HPS_IOB_1,_GPIO1_IO0,_SPIM1_CLK,_UART0_CTS_N,_NAND_ADQ0,_EMAC1_TX_CLK) U7.38(INT_N/PME_N2)
ENET_LED1: Q4.1(GATE) R138.2 R139.1 U7.17(LED1_PHYAD0/PME_N1)
ENET_LED2: Q2.1(GATE) R136.2 R137.1 U7.15(LED2_PHYAD1)
ENET_MDC: R156.2 U2.F3(HPS_IOB_24,_GPIO1_IO23,_SPIM0_SS0_N,_SPIS1_MISO,_MDIO0_MDC,_I2C_EMAC0_SCL,_NAND_ADQ15,_EMAC2_RXD3) U7.36(MDC)
ENET_MDIO: R157.2 U2.AD13(HPS_IOB_23,_GPIO1_IO22,_SPIM0_MISO,_SPIS1_SS0_N,_MDIO0_MDIO,_I2C_EMAC0_SDA,_NAND_ADQ14,_EMAC2_RXD2) U7.37(MDIO)
ENET_RSET: R135.1 U7.48(ISET)
ENET_RSTn: R159.2 U7.42(RESET_N) ; also on sheet 43
ENET_RX_CLK: R127.2 U2.AA4(HPS_IOA_15,_GPIO0_IO14,_NAND_CE_N,_USB1_DIR,_EMAC0_RX_CLK)
ENET_RX_DV: R129.2 U2.T1(HPS_IOA_16,_GPIO0_IO15,_USB1_DATA0,_EMAC0_RX_CTL)
ENET_RXD0: R130.2 U2.AF7(HPS_IOA_19,_GPIO0_IO18,_NAND_ADQ10,_USB1_DATA2,_EMAC0_RXD0)
ENET_RXD1: R131.2 U2.M1(HPS_IOA_20,_GPIO0_IO19,_SPIM1_SS1_N,_NAND_ADQ11,_USB1_DATA3,_EMAC0_RXD1)
ENET_RXD2: R132.2 U2.AB5(HPS_IOA_23,_GPIO0_IO22,_SPIM1_MISO,_SPIS0_SS0_N,_UART0_TX,_I2C0_SDA,_NAND_ADQ14,_USB1_DATA6,_EMAC0_RXD2)
ENET_RXD3: R133.2 U2.U2(HPS_IOA_24,_GPIO0_IO23,_SPIM1_SS0_N,_SPIS0_MISO,_UART0_RX,_I2C0_SCL,_NAND_ADQ15,_USB1_DATA7,_EMAC0_RXD3)
ENET_TX_EN: U2.V1(HPS_IOA_14,_GPIO0_IO13,_NAND_RB,_USB1_STP,_EMAC0_TX_CTL) U7.25(TX_EN)
ENET_TXD0: U2.AD5(HPS_IOA_17,_GPIO0_IO16,_NAND_ADQ8,_USB1_DATA1,_EMAC0_TXD0) U7.19(TXD0)
ENET_TXD1: U2.P1(HPS_IOA_18,_GPIO0_IO17,_NAND_ADQ9,_USB1_NXT,_EMAC0_TXD1) U7.20(TXD1)
ENET_TXD2: U2.AF9(HPS_IOA_21,_GPIO0_IO20,_SPIM1_CLK,_SPIS0_CLK,_UART0_CTS_N,_I2C1_SDA,_NAND_ADQ12,_USB1_DATA4,_EMAC0_TXD2) U7.21(TXD2)
ENET_TXD3: U2.W2(HPS_IOA_22,_GPIO0_IO21,_SPIM1_MOSI,_SPIS0_MOSI,_UART0_RTS_N,_I2C1_SCL,_NAND_ADQ13,_USB1_DATA5,_EMAC0_TXD3) U7.22(TXD3)
ENET_VDD1.2V: C225.2 C233.1 C234.1 L5.1 L6.1 L7.1 R164.1 R165.2 U8.1(VOUT1) U8.2(VOUT2)
ENET_XI: R161.2 U7.46(XI)
FPGA_CONF_DONE: R123.2 U2.CA60(SDM_IO16,_INIT_DONE,_CONF_DONE,_PWRMGT_SDA) ; also on sheet 41 44
FPGA_CVP_CONFDONE: R124.2 R5773.2 ; also on sheet 41 44
FPGA_INIT_DONE: R122.2 U2.CF59(SDM_IO0,_INIT_DONE,_PWRMGT_PWM0,_PWRMGT_SCL) ; also on sheet 44
FPGA_JTAG_TCK: R119.2 U2.CU62(TCK) ; also on sheet 44
FPGA_JTAG_TDI: R118.2 U2.CV61(TDI) ; also on sheet 44
FPGA_JTAG_TDO: U2.CR62(TDO) ; also on sheet 44
FPGA_JTAG_TMS: R117.2 U2.CT61(TMS) ; also on sheet 44
FPGA_NCONFIG: R121.2 U2.CB57(NCONFIG) ; also on sheet 44
FPGA_NSTATUS: R120.2 U2.CH59(NSTATUS)
FPGA_OSC_CLK_1: U2.CC60(OSC_CLK_1) ; also on sheet 38
FPGA_SDM_SCL: U2.CG60(SDM_IO14,_AVSTX8_CLK,_PWRMGT_SCL,_NAND_ADQ7) ; also on sheet 40
FPGA_SDM_SDA: U2.CE60(SDM_IO11,_AVSTX8_VALID,_PWRMGT_SDA,_NAND_ADQ6) ; also on sheet 40
FPGA_TEMP0n: U2.CA52(TEMPDIODE0AN) ; also on sheet 47
FPGA_TEMP0p: U2.CC52(TEMPDIODE0AP) ; also on sheet 47
FT232R_3V3OUT: C249.2 C250.1 R171.1 U11.16(3V3OUT)
FT232R_RXD: U10.4(Y) U11.2(RXD)
FT232R_TXD: U9.2(A) U11.30(TXD)
FT232R_VCCIO: C244.1 C247.1 C251.2 C252.1 C253.1 D2.A(ANODE) D3.A(ANODE) R167.2 R171.2 R172.1 R179.2 U10.5(VCC) U11.1(VCCIO) U12.5(VCC)
HPS_I2C_SCL: U2.L2(HPS_IOB_8,_GPIO1_IO7,_SPIS1_MISO,_UART1_RX,_I2C1_SCL,_NAND_CLE,_EMAC1_RXD1) ; also on sheet 40
HPS_I2C_SDA: U2.AB7(HPS_IOB_7,_GPIO1_IO6,_SPIS1_SS0_N,_UART1_TX,_I2C1_SDA,_NAND_ADQ3,_EMAC1_RXD0) ; also on sheet 40
HPS_OSC_CLK: U2.AD11(HPS_IOB_19,_GPIO1_IO18,_SPIM0_MISO,_MDIO1_MDIO,_I2C_EMAC1_SDA,_NAND_ADQ10,_SDMMC_DATA4,_EMAC2_RXD0) ; also on sheet 38
HPS_RESETn: R125.2 U2.CB59(SDM_IO13,_AVSTX8_DATA5,_SDMMC_CFG_DATA5,_NAND_CE_N) ; also on sheet 44
IO_1p8V: C207.1 C208.1 C243.1 L4.1 R107.2 R108.2 R109.2 R116.1 R117.1 R118.1 R120.1 R121.1 R122.1 R123.1 R124.1 R125.1 R140.1 R143.1 R156.1 R157.1 R158.1 R159.1 R174.2 R5774.1 U6.B4(VCC) U9.5(VCC) ; also on sheet 30 31 34 38 39 40 46 57 65
IO_3p3V: C173.1 C174.1 C226.2 C229.1 L3.1 R98.2 R99.2 R102.2 R103.2 R104.1 R105.2 R106.1 R126.1 R134.1 R162.1 R163.2 R832.1 U5.14(VCC) U8.9(VIN2) U8.10(VIN1) ; also on sheet 12 23 24 30 31 38 39 40 41 42 63
LINK_LED: J8.17(GK) L1.2
MDI_HPS_N0: J8.10(TD0_N) U7.3(TXRXM_A)
MDI_HPS_N1: J8.5(TD1_N) U7.6(TXRXM_B)
MDI_HPS_N2: J8.2(TD2_N) U7.8(TXRXM_C)
MDI_HPS_N3: J8.9(TD3_N) U7.11(TXRXM_D)
MDI_HPS_P0: J8.11(TD0_P) U7.2(TXRXP_A)
MDI_HPS_P1: J8.4(TD1_P) U7.5(TXRXP_B)
MDI_HPS_P2: J8.3(TD2_P) U7.7(TXRXP_C)
MDI_HPS_P3: J8.8(TD3_P) U7.10(TXRXP_D)
MICTOR_JTAG_TCK: U2.AC8(HPS_IOB_9,_GPIO1_IO8,_JTAG_TCK,_SPIS0_CLK,_MDIO2_MDIO,_I2C_EMAC2_SDA,_NAND_ADQ4,_EMAC1_TXD2) ; also on sheet 30
MICTOR_JTAG_TDI: U2.G2(HPS_IOB_12,_GPIO1_IO11,_JTAG_TDI,_SPIS0_MISO,_MDIO0_MDC,_I2C_EMAC0_SCL,_NAND_ADQ7,_EMAC1_RXD3) ; also on sheet 30
MICTOR_JTAG_TDO: U2.AA8(HPS_IOB_11,_GPIO1_IO10,_JTAG_TDO,_SPIS0_SS0_N,_MDIO0_MDIO,_I2C_EMAC0_SDA,_NAND_ADQ6,_EMAC1_RXD2) ; also on sheet 30
MICTOR_JTAG_TMS: U2.J2(HPS_IOB_10,_GPIO1_IO9,_JTAG_TMS,_SPIS0_MOSI,_MDIO2_MDC,_I2C_EMAC2_SCL,_NAND_ADQ5,_EMAC1_TXD3) ; also on sheet 30
MSEL1: R108.1 SW1.2(A2) U2.CY59(SDM_IO7,_AS_NCSO2,_NAND_ALE,_MSEL1)
MSEL2: R109.1 SW1.3(A3) U2.CV59(SDM_IO9,_AS_NCSO1,_NAND_CLE,_MSEL2)
PCIE_1V2_CLKREQn: R833.2 U5.5(IOVL4) ; also on sheet 19
PCIE_CLKREQn: C1472.1 J7.B12(RSVD1) R832.2 U5.10(IOVCC4)
PCIE_EP_3p3V: J7.A9(+3_3V) J7.A10(+3_3V) J7.B8(+3_3V) R100.2
PCIE_EP_3V3_I2C_SCL: J7.B5(SMCLK) R98.1 U5.13(IOVCC1) ; also on sheet 44
PCIE_EP_3V3_I2C_SDA: J7.B6(SMDAT) R99.1 U5.12(IOVCC2) ; also on sheet 44
PCIE_EP_3V3_WAKEN: R101.2 R106.2 U5.11(IOVCC3)
PCIE_EP_12V: J7.A2(+12V) J7.A3(+12V) J7.B1(+12V) J7.B2(+12V) J7.B3(+12V) ; also on sheet 48
PCIE_EP_I2C_SCL: U5.2(IOVL1) ; also on sheet 19
PCIE_EP_I2C_SDA: U5.3(IOVL2) ; also on sheet 19
PCIE_EP_JTAG_TCK: J7.A5(JTAG_TCK) ; also on sheet 44
PCIE_EP_JTAG_TDI: J7.A6(JTAG_TDI) R102.1 ; also on sheet 44
PCIE_EP_JTAG_TDO: J7.A7(JTAG_TDO) ; also on sheet 44
PCIE_EP_JTAG_TMS: J7.A8(JTAG_TMS) R103.1 ; also on sheet 44
PCIE_EP_PERSTN: J7.A11(PERST_N) R105.1 ; also on sheet 43 47
PCIE_EP_PRSNT_N: J7.A1(PRSNT1_N) SW6.1(A1) SW6.2(A2) SW6.3(A3) SW6.4(A4)
PCIE_EP_PRSNT_Nx1: C1479.1 J7.B17(PRSNT2n_X1) SW6.5(B4)
PCIE_EP_PRSNT_Nx4: C1480.1 J7.B31(PRSNT2n_X4) SW6.6(B3)
PCIE_EP_PRSNT_Nx8: C1481.1 J7.B48(PRSNT2n_X8) SW6.7(B2)
PCIE_EP_PRSNT_Nx16: C1482.1 J7.B81(PRSNT2n_X16) SW6.8(B1)
PCIE_EP_RX_CN0: C175.1 J7.A17(PER0N)
PCIE_EP_RX_CN1: C178.1 J7.A22(PER1N)
PCIE_EP_RX_CN2: C180.1 J7.A26(PER2N)
PCIE_EP_RX_CN3: C182.1 J7.A30(PER3N)
PCIE_EP_RX_CN4: C184.1 J7.A36(PER4N)
PCIE_EP_RX_CN5: C186.1 J7.A40(PER5N)
PCIE_EP_RX_CN6: C188.1 J7.A44(PER6N)
PCIE_EP_RX_CN7: C190.1 J7.A48(PER7N)
PCIE_EP_RX_CN8: C192.1 J7.A53(PER8N)
PCIE_EP_RX_CN9: C194.1 J7.A57(PER9N)
PCIE_EP_RX_CN10: C196.1 J7.A61(PER10N)
PCIE_EP_RX_CN11: C198.1 J7.A65(PER11N)
PCIE_EP_RX_CN12: C200.1 J7.A69(PER12N)
PCIE_EP_RX_CN13: C202.1 J7.A73(PER13N)
PCIE_EP_RX_CN14: C204.1 J7.A77(PER14N)
PCIE_EP_RX_CN15: C206.1 J7.A81(PER15N)
PCIE_EP_RX_CP0: C172.1 J7.A16(PER0P)
PCIE_EP_RX_CP1: C177.1 J7.A21(PER1P)
PCIE_EP_RX_CP2: C179.1 J7.A25(PER2P)
PCIE_EP_RX_CP3: C181.1 J7.A29(PER3P)
PCIE_EP_RX_CP4: C183.1 J7.A35(PER4P)
PCIE_EP_RX_CP5: C185.1 J7.A39(PER5P)
PCIE_EP_RX_CP6: C187.1 J7.A43(PER6P)
PCIE_EP_RX_CP7: C189.1 J7.A47(PER7P)
PCIE_EP_RX_CP8: C191.1 J7.A52(PER8P)
PCIE_EP_RX_CP9: C193.1 J7.A56(PER9P)
PCIE_EP_RX_CP10: C195.1 J7.A60(PER10P)
PCIE_EP_RX_CP11: C197.1 J7.A64(PER11P)
PCIE_EP_RX_CP12: C199.1 J7.A68(PER12P)
PCIE_EP_RX_CP13: C201.1 J7.A72(PER13P)
PCIE_EP_RX_CP14: C203.1 J7.A76(PER14P)
PCIE_EP_RX_CP15: C205.1 J7.A80(PER15P)
PCIE_EP_RX_N0: C175.2 ; also on sheet 22
PCIE_EP_RX_N1: C178.2 ; also on sheet 22
PCIE_EP_RX_N2: C180.2 ; also on sheet 22
PCIE_EP_RX_N3: C182.2 ; also on sheet 22
PCIE_EP_RX_N4: C184.2 ; also on sheet 22
PCIE_EP_RX_N5: C186.2 ; also on sheet 22
PCIE_EP_RX_N6: C188.2 ; also on sheet 22
PCIE_EP_RX_N7: C190.2 ; also on sheet 22
PCIE_EP_RX_N8: C192.2 ; also on sheet 22
PCIE_EP_RX_N9: C194.2 ; also on sheet 22
PCIE_EP_RX_N10: C196.2 ; also on sheet 22
PCIE_EP_RX_N11: C198.2 ; also on sheet 22
PCIE_EP_RX_N12: C200.2 ; also on sheet 22
PCIE_EP_RX_N13: C202.2 ; also on sheet 22
PCIE_EP_RX_N14: C204.2 ; also on sheet 22
PCIE_EP_RX_N15: C206.2 ; also on sheet 22
PCIE_EP_RX_P0: C172.2 ; also on sheet 22
PCIE_EP_RX_P1: C177.2 ; also on sheet 22
PCIE_EP_RX_P2: C179.2 ; also on sheet 22
PCIE_EP_RX_P3: C181.2 ; also on sheet 22
PCIE_EP_RX_P4: C183.2 ; also on sheet 22
PCIE_EP_RX_P5: C185.2 ; also on sheet 22
PCIE_EP_RX_P6: C187.2 ; also on sheet 22
PCIE_EP_RX_P7: C189.2 ; also on sheet 22
PCIE_EP_RX_P8: C191.2 ; also on sheet 22
PCIE_EP_RX_P9: C193.2 ; also on sheet 22
PCIE_EP_RX_P10: C195.2 ; also on sheet 22
PCIE_EP_RX_P11: C197.2 ; also on sheet 22
PCIE_EP_RX_P12: C199.2 ; also on sheet 22
PCIE_EP_RX_P13: C201.2 ; also on sheet 22
PCIE_EP_RX_P14: C203.2 ; also on sheet 22
PCIE_EP_RX_P15: C205.2 ; also on sheet 22
PCIE_EP_TX_N0: J7.B15(PET0N) ; also on sheet 22
PCIE_EP_TX_N1: J7.B20(PET1N) ; also on sheet 22
PCIE_EP_TX_N2: J7.B24(PET2N) ; also on sheet 22
PCIE_EP_TX_N3: J7.B28(PET3N) ; also on sheet 22
PCIE_EP_TX_N4: J7.B34(PET4N) ; also on sheet 22
PCIE_EP_TX_N5: J7.B38(PET5N) ; also on sheet 22
PCIE_EP_TX_N6: J7.B42(PET6N) ; also on sheet 22
PCIE_EP_TX_N7: J7.B46(PET7N) ; also on sheet 22
PCIE_EP_TX_N8: J7.B51(PET8N) ; also on sheet 22
PCIE_EP_TX_N9: J7.B55(PET9N) ; also on sheet 22
PCIE_EP_TX_N10: J7.B59(PET10N) ; also on sheet 22
PCIE_EP_TX_N11: J7.B63(PET11N) ; also on sheet 22
PCIE_EP_TX_N12: J7.B67(PET12N) ; also on sheet 22
PCIE_EP_TX_N13: J7.B71(PET13N) ; also on sheet 22
PCIE_EP_TX_N14: J7.B75(PET14N) ; also on sheet 22
PCIE_EP_TX_N15: J7.B79(PET15N) ; also on sheet 22
PCIE_EP_TX_P0: J7.B14(PET0P) ; also on sheet 22
PCIE_EP_TX_P1: J7.B19(PET1P) ; also on sheet 22
PCIE_EP_TX_P2: J7.B23(PET2P) ; also on sheet 22
PCIE_EP_TX_P3: J7.B27(PET3P) ; also on sheet 22
PCIE_EP_TX_P4: J7.B33(PET4P) ; also on sheet 22
PCIE_EP_TX_P5: J7.B37(PET5P) ; also on sheet 22
PCIE_EP_TX_P6: J7.B41(PET6P) ; also on sheet 22
PCIE_EP_TX_P7: J7.B45(PET7P) ; also on sheet 22
PCIE_EP_TX_P8: J7.B50(PET8P) ; also on sheet 22
PCIE_EP_TX_P9: J7.B54(PET9P) ; also on sheet 22
PCIE_EP_TX_P10: J7.B58(PET10P) ; also on sheet 22
PCIE_EP_TX_P11: J7.B62(PET11P) ; also on sheet 22
PCIE_EP_TX_P12: J7.B66(PET12P) ; also on sheet 22
PCIE_EP_TX_P13: J7.B70(PET13P) ; also on sheet 22
PCIE_EP_TX_P14: J7.B74(PET14P) ; also on sheet 22
PCIE_EP_TX_P15: J7.B78(PET15P) ; also on sheet 22
PCIE_EP_WAKEN: U5.4(IOVL3) ; also on sheet 19
PCIE_PWRBRKN: C1474.1 J7.B30(RSVD3) R794.2 ; also on sheet 44 47
PCIE_RSV2: C1473.1 J7.A19(RSVD2)
PCIE_RSV4: C1475.1 J7.A32(RSVD4)
PCIE_RSV5: C1476.1 J7.A33(RSVD5)
PCIE_RSV6: C1477.1 J7.B82(RSVD6)
PCIE_RSV7: C1478.1 J7.A50(RSVD7)
PHY_25M_3.3V: C227.2 C228.2 R160.1 R162.2 Y1.4(VCC)
PWR_ENA: R179.1 U11.11(CBUS3)
QSPI_RESETn: R5772.2 R5774.2 U2.CA58(SDM_IO15,_AVSTX8_DATA6,_SDMMC_CFG_DATA6,_NAND_ADQ4)
REFCLK_PCIE_EP_EDGE_N: J7.A14(REFCLK-) ; also on sheet 39
REFCLK_PCIE_EP_EDGE_P: J7.A13(REFCLK+) ; also on sheet 39
RSV_SD_RESETn: U2.AA2(HPS_IOA_12,_GPIO0_IO11,_SPIM1_SS0_N,_SPIS1_MISO,_MDIO0_MDC,_I2C_EMAC0_SCL,_NAND_ADQ7,_USB0_DATA7) ; also on sheet 44
SD_CLK: U2.AB9(HPS_IOB_15,_GPIO1_IO14,_UART1_TX,_NAND_CE_N,_SDMMC_CCLK,_EMAC2_RX_CLK) ; also on sheet 30
SD_CMD: U2.V3(HPS_IOB_14,_GPIO1_IO13,_I2C1_SCL,_NAND_RB,_SDMMC_CMD,_EMAC2_TX_CTL) ; also on sheet 30
SD_DATA0: U2.AD9(HPS_IOB_13,_GPIO1_IO12,_I2C1_SDA,_NAND_ALE,_SDMMC_DATA0,_EMAC2_TX_CLK) ; also on sheet 30
SD_DATA1: U2.T3(HPS_IOB_16,_GPIO1_IO15,_UART1_RX,_SDMMC_DATA1,_EMAC2_RX_CTL) ; also on sheet 30
SD_DATA2: U2.AC10(HPS_IOB_17,_GPIO1_IO16,_UART1_CTS_N,_NAND_ADQ8,_SDMMC_DATA2,_EMAC2_TXD0) ; also on sheet 30
SD_DATA3: U2.P3(HPS_IOB_18,_GPIO1_IO17,_SPIM0_SS1_N,_UART1_RTS_N,_NAND_ADQ9,_SDMMC_DATA3,_EMAC2_TXD1) ; also on sheet 30
UART_EN: R167.1 U9.1(OE) ; also on sheet 39
UART_RESETn: R172.2 R175.2 U11.18(~{RESET})
UART_RSTn: R174.1 U12.2(A) ; also on sheet 43
UART_RX: J9.1 R169.1 U2.F1(HPS_IOB_4,_GPIO1_IO3,_SPIM1_SS0_N,_UART0_RX,_I2C0_SCL,_NAND_RE_N,_EMAC1_RX_CTL)
UART_RX_LED: R178.1 U11.21(CBUS1)
UART_TX: J9.2 U2.AA6(HPS_IOB_3,_GPIO1_IO2,_SPIM1_MISO,_UART0_TX,_I2C0_SDA,_NAND_WE_N,_EMAC1_RX_CLK) U10.2(A)
UART_TX_LED: R177.1 U11.22(CBUS0)
UART_USB_PGND: C248.2 J10.6(SHELL1) J10.7(SHELL2) J10.8(SHELL3) J10.9(SHELL4) R176.2
USB_UART_5V: C254.2 C255.1 L8.1 U11.19(VCC) U13.6(VBUS)
USB_UART_CON_5V: C256.2 C257.1 J10.1(VBUS) L8.2
USB_UART_DM: C245.1 J10.2(D-) U11.15(USBDM) U13.1(D+)
USB_UART_DP: C246.1 J10.3(D+) U11.14(USBDP) U13.2(D-)
N31250983: J7.B11(WAKE_N) R101.1
N31253181: J7.B9(JTAG_TRSTN) R104.2
N31257069: J7.B10(+3_3VAUX) R100.1
N35659314: R114.2 U2.CA54(RREF_SDM)
N35660053: C209.1 R116.2 R814.1 U2.CC62(VREFP_ADC) U52.1(VO)
N35951410: C210.1 J8.14(YA) R126.2
N35951471: R128.1 U7.24(GTX_CLK)
N35951814: C215.2 J8.16(GOA) R134.2
N35952167: L1.1 Q1.3(DRAIN)
N35952169: Q1.1(GATE) Q2.3(DRAIN) R140.2
N35952204: L2.1 Q3.3(DRAIN)
N35952206: Q3.1(GATE) Q4.3(DRAIN) R143.2
N35952591: R160.2 Y1.1(EN)
N35952937: C225.1 R164.2 R166.2 U8.3(VFB)
N35952961: R163.1 U8.7(EN)
N35952969: R165.1 U8.4(POK)
N35953003: C235.2 U8.6(SS)
N35980126: R169.2 U9.4(Y)
N35980394: J10.4(ID) R173.1
N35980546: R175.1 U12.4(Y)
N35980606: D2.C(CATHODE) R177.2
N35980632: D3.C(CATHODE) R178.2
N36112579: R112.2 SW1.6(B3)
N36112582: R111.2 SW1.7(B2)
N36112585: R110.2 SW1.8(B1)
N36396769: U7.43(LDO_O) V1.1(TP)
N37651435: C1472.2 R773.2
N37651438: C1473.2 R774.2
N37651441: C1474.2 R775.2
N37651444: C1475.2 R776.2
N37651447: C1476.2 R777.2
N37651450: C1477.2 R778.2
N37651453: C1478.2 R779.2
N37651456: C1479.2 R780.2
N37651459: C1480.2 R781.2
N37651462: C1481.2 R782.2
N37651465: C1482.2 R783.2
N39014223: R5772.1 U6.A4(RESET#/DNU)
N39025445: R5773.1 U2.CC58(SDM_IO10,_AVSTX8_DATA7,_SDMMC_CFG_DATA7,_NAND_ADQ5)
N42842693: R161.1 Y1.3(OUT)

Not connected (* = marked no-connect by the designer): J8 15(OK)*; SW1 4(A4)* 5(B4)*; U2 AC12(HPS_IOB_21,_GPIO1_IO20,_SPIM0_CLK,_SPIS1_CLK,_I2C_EMAC2_SDA,_NAND_ADQ12,_SDMMC_DATA6,_EMAC2_TXD2)* AD7(HPS_IOB_5,_GPIO1_IO4,_SPIM1_SS1_N,_SPIS1_CLK,_UART1_CTS_N,_NAND_WP_N,_EMAC1_TXD0)* AF3(HPS_IOA_11,_GPIO0_IO10,_SPIM1_MISO,_SPIS1_SS0_N,_MDIO0_MDIO,_I2C_EMAC0_SDA,_NAND_ADQ6,_USB0_DATA6)* AH19(DNU6)* AJ20(DNU7)* BY53(DNU5)* BY55(DNU3)* CB53(DNU4)* CC56(SDM_IO12,_PWRMGT_PWM0,_PWRMGT_SDA,_NAND_WP_N)* CF61(DNU1)* CH61(DNU2)* CL60(SDM_IO8,AVST_READY,AS_NCSO3,SDMMC_CFG_DATA4,NAND_RB)* H1(HPS_IOB_2,_GPIO1_IO1,_SPIM1_MOSI,_UART0_RTS_N,_NAND_ADQ1,_EMAC1_TX_CTL)* H3(HPS_IOB_22,_GPIO1_IO21,_SPIM0_MOSI,_SPIS1_MOSI,_I2C_EMAC2_SCL,_NAND_ADQ13,_SDMMC_DATA7,_EMAC2_TXD3)* M3(HPS_IOB_20,_GPIO1_IO19,_SPIM0_SS0_N,_MDIO1_MDC,_I2C_EMAC1_SCL,_NAND_ADQ11,_SDMMC_DATA5,_EMAC2_RXD1)* N2(HPS_IOB_6,_GPIO1_IO5,_SPIS1_MOSI,_UART1_RTS_N,_NAND_ADQ2,_EMAC1_TXD1)*; U5 6(NC0)* 9(NC1)*; U6 A2(DNU1)* A3(DNU2)* A5(DNU3)* B1(DNU4)* B5(DNU5)* C1(DNU6)* C3(DNU7)* C5(DNU8)* D1(DNU9)* D5(DNU10)* E1(DNU11)* E2(DNU12)* E3(DNU13)* E4(DNU14)* E5(DNU15)*; U7 13(NC)* 45(XO)* 47(NC1)*; U8 8(NC)*; U10 1(NC)*; U11 3(~{RI})* 5(NC3)* 6(~{DSR})* 7(~{DCD})* 8(~{CTS})* 9(CBUS4)* 10(CBUS2)* 12(NC4)* 13(NC5)* 23(NC2)* 25(NC1)* 27(OSCI)* 28(OSCO)* 29(NC6)* 31(~{DTR})* 32(~{RTS})*; U12 1(NC)*; U13 3(ID)* 5(NC)*; U52 3(NC)*

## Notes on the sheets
sheet 25
- PCIe Endpoint Edge Connector
- Notes: Close --> select;
         Open --> deselect
- PCIE TX to FPGA RX
  P/N Lane Reversal during layout is allowed
- PCIE RX from FPGA TX
  P/N Lane Reversal during layout is allowed
- move R794 to near U26 or U30
  for easy power split of 3p3V_STBY
- Note: Place near to golden finger
- PCIe TX/RX signal naming convention
  with respect to CPU
sheet 26
- SDM & Configuration
- Config Mode         MSEL2     MSEL1     MSEL0
    AS_FAST                 0               0             1
   AS_NORMAL           0               1             1
sheet 27
- Bank HPS
sheet 28
- 10/100/1000 Ethernet - HPS
- Ethernet Interface
- No Activity:  OFF
- Activity (RX, TX) : Blinking
- NAME
- Pin
- Value
- Description
- PHYAD2
- 35
- 1
- ID = b"100"
- On-Chip Termination Resistors for the Differential Pairs
- PHYAD1
- 15
- 0
- PHYAD0
- 17
- 0
- RGMII
  (10/100/1000 half-/full-duplex)
- MODE3
- 27
- 1
- MODE2
- 28
- 1
- MODE1
- 31
- 1
- MODE0
- 32
- 1
- ClK125_EN
- 33
- 0
- No clockoutput from pin41
- Link OFF
- Link ON
- LED_MODE
- 41
- 1
- single led
  mode
- Activity
- Link
- BOOT-STRAPS
- Place near KSZ9031RN PHY
- Use AVDDH supply for the crystal/clock pins (XI, XO)
- Ethernet 1.2V LDO
- 250mA Max.
- PUS: AVDDH/DVDDH before 1.2V core
sheet 29
- USB-UART Port
- OE=L
  A=X (Floating input allowed)
  Y=Z
- Debugging Loopback
  disable U9 and short J9
- WE 651005136421
